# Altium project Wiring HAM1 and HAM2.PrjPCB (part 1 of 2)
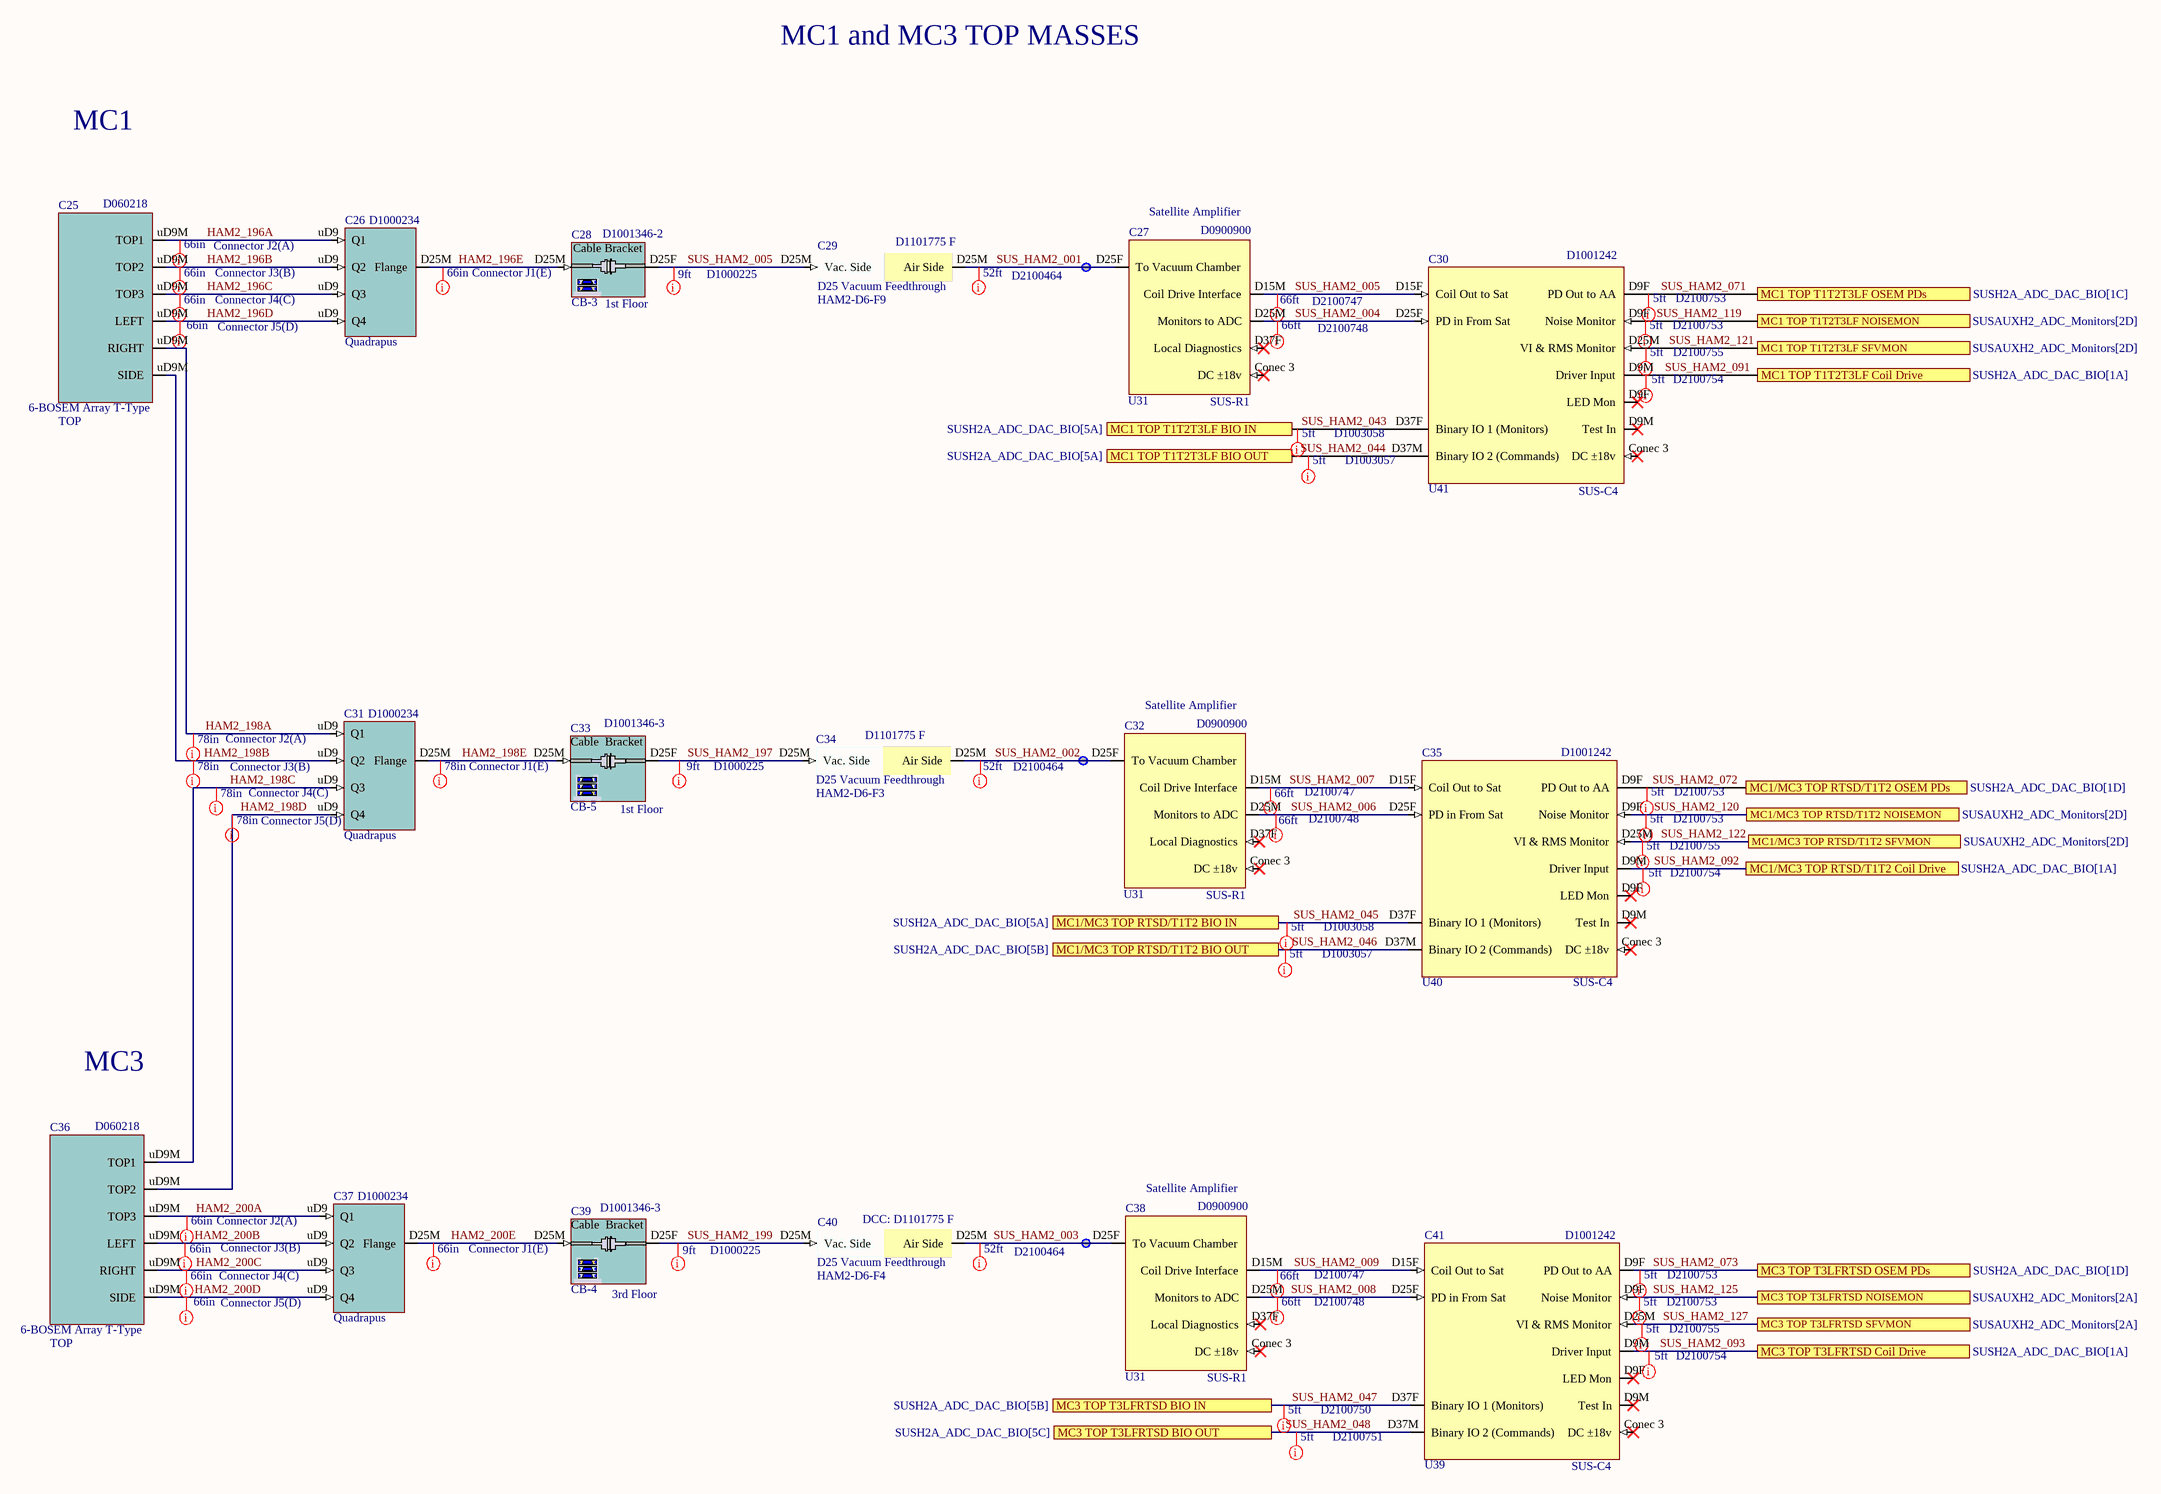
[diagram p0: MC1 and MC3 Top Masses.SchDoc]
14 sheets, 198 parts. Net scope: flat (ports and power ports of the same name join across sheets).
Sheets:
  MC1 and MC3 Top Masses.SchDoc
  PRM and PR3 Top Masses.SchDoc
  MC1 Middle and Bottom.SchDoc
  MC3 Middle and Bottom.SchDoc
  PRM Middle and Bottom.SchDoc
  PR3 Middle and Bottom.SchDoc
  IM1_IM2_IM3_IM4_OSEMs.SchDoc
  RM1_RM2.SchDoc
  JMX_PM1.SchDoc
  SUSH2A_ADC_DAC_BIO.SchDoc
  SUSH2B_ADC_DAC_BIO.SchDoc
  SUSAUXH2_ADC_Monitors.SchDoc
  RACK_SUS_R1_R2.SchDoc
  RACK_SUS_C3_C4.SchDoc

## Sheet MC1 and MC3 Top Masses.SchDoc: MC1 and MC3 Top Masses
size C; Organization: LIGO Laboratory; Address1: California Institute of Technology; Address2: Massachusetts Institute of Technology; DocumentNumber: D0902810; Revision: v11; SheetNumber: 1; SheetTotal: 14; Engineer: J.Kissel/L.Sánchez

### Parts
C25  6-BOSEM Array T-Type  Parameter 1: TOP  DCC: D060218
C26  Quadrapus  DCC: D1000234
C27  Satellite Amplifier  Slot: U31  Rack: SUS-R1  DCC: D0900900
C28  Rack: CB-3  Slot: 1st Floor  DCC: D1001346-2  (hidden comment: Cable Bracket)
C29  D25 Vacuum Feedthrough  value HAM2-D6-F9  DCC: D1101775 F
C30  Slot: U41  Rack: SUS-C4  DCC: D1001242  (hidden comment: CD Triple Top D1001242)
C31  Quadrapus  DCC: D1000234
C32  Satellite Amplifier  Slot: U31  Rack: SUS-R1  DCC: D0900900
C33  Rack: CB-5  Slot: 1st Floor  DCC: D1001346-3  (hidden comment: D1001346-3 1st Cable Bracket)
C34  D25 Vacuum Feedthrough  value HAM2-D6-F3  DCC: D1101775 F
C35  Slot: U40  Rack: SUS-C4  DCC: D1001242  (hidden comment: CD Triple Top D1001242)
C36  6-BOSEM Array T-Type  Parameter 1: TOP  DCC: D060218
C37  Quadrapus  DCC: D1000234
C38  Satellite Amplifier  Slot: U31  Rack: SUS-R1  DCC: D0900900
C39  Rack: CB-4  DCC: D1001346-3  Slot: 3rd Floor  (hidden comment: D1001346-3 3rd Cable Bracket)
C40  D25 Vacuum Feedthrough  value HAM2-D6-F4  DCC: D1101775 F
C41  Slot: U39  Rack: SUS-C4  DCC: D1001242  (hidden comment: CD Triple Top D1001242)

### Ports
MC1 TOP T1T2T3LF BIO IN (see SUSH2A_ADC_DAC_BIO[5A]), MC1 TOP T1T2T3LF BIO OUT (see SUSH2A_ADC_DAC_BIO[5A]), MC1 TOP T1T2T3LF Coil Drive (see SUSH2A_ADC_DAC_BIO[1A]), MC1 TOP T1T2T3LF NOISEMON (see SUSAUXH2_ADC_Monitors[2D]), MC1 TOP T1T2T3LF OSEM PDs (see SUSH2A_ADC_DAC_BIO[1C]), MC1 TOP T1T2T3LF SFVMON (see SUSAUXH2_ADC_Monitors[2D]), MC1/MC3 TOP RTSD/T1T2 BIO IN (see SUSH2A_ADC_DAC_BIO[5A]), MC1/MC3 TOP RTSD/T1T2 BIO OUT (see SUSH2A_ADC_DAC_BIO[5B]), MC1/MC3 TOP RTSD/T1T2 Coil Drive (see SUSH2A_ADC_DAC_BIO[1A]), MC1/MC3 TOP RTSD/T1T2 NOISEMON (see SUSAUXH2_ADC_Monitors[2D]), MC1/MC3 TOP RTSD/T1T2 OSEM PDs (see SUSH2A_ADC_DAC_BIO[1D]), MC1/MC3 TOP RTSD/T1T2 SFVMON (see SUSAUXH2_ADC_Monitors[2D]), MC3 TOP T3LFRTSD BIO IN (see SUSH2A_ADC_DAC_BIO[5B]), MC3 TOP T3LFRTSD BIO OUT (see SUSH2A_ADC_DAC_BIO[5C]), MC3 TOP T3LFRTSD Coil Drive (see SUSH2A_ADC_DAC_BIO[1A]), MC3 TOP T3LFRTSD NOISEMON (see SUSAUXH2_ADC_Monitors[2A]), MC3 TOP T3LFRTSD OSEM PDs (see SUSH2A_ADC_DAC_BIO[1D]), MC3 TOP T3LFRTSD SFVMON (see SUSAUXH2_ADC_Monitors[2A])

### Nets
HAM2_196A: C25.uD9M(TOP1) C26.uD9(Q1)
HAM2_196B: C25.uD9M(TOP2) C26.uD9(Q2)
HAM2_196C: C25.uD9M(TOP3) C26.uD9(Q3)
HAM2_196D: C25.uD9M(LEFT) C26.uD9(Q4)
HAM2_196E: C26.D25M(Flange) C28.D25M
HAM2_198A: C25.uD9M(RIGHT) C31.uD9(Q1)
HAM2_198B: C25.uD9M(SIDE) C31.uD9(Q2)
HAM2_198C: C31.uD9(Q3) C36.uD9M(TOP1)
HAM2_198D: C31.uD9(Q4) C36.uD9M(TOP2)
HAM2_198E: C31.D25M(Flange) C33.D25M
HAM2_200A: C36.uD9M(TOP3) C37.uD9(Q1)
HAM2_200B: C36.uD9M(LEFT) C37.uD9(Q2)
HAM2_200C: C36.uD9M(RIGHT) C37.uD9(Q3)
HAM2_200D: C36.uD9M(SIDE) C37.uD9(Q4)
HAM2_200E: C37.D25M(Flange) C39.D25M
SUS_HAM2_001: C27.D25F(To_Vacuum_Chamber) C29.D25M(Air_Side)
SUS_HAM2_002: C32.D25F(To_Vacuum_Chamber) C34.D25M(Air_Side)
SUS_HAM2_003: C38.D25F(To_Vacuum_Chamber) C40.D25M(Air_Side)
SUS_HAM2_004: C27.D25M(Monitors_to_ADC) C30.D25F(PD_in_From_Sat)
SUS_HAM2_005: C27.D15M(Coil_Drive_Interface) C28.D25F C29.D25M(Vac._Side) C30.D15F(Coil_Out_to_Sat)
SUS_HAM2_006: C32.D25M(Monitors_to_ADC) C35.D25F(PD_in_From_Sat)
SUS_HAM2_007: C32.D15M(Coil_Drive_Interface) C35.D15F(Coil_Out_to_Sat)
SUS_HAM2_008: C38.D25M(Monitors_to_ADC) C41.D25F(PD_in_From_Sat)
SUS_HAM2_009: C38.D15M(Coil_Drive_Interface) C41.D15F(Coil_Out_to_Sat)
SUS_HAM2_043: C30.D37F(Binary_IO_1_(Monitors)) ; port MC1 TOP T1T2T3LF BIO IN
SUS_HAM2_044: C30.D37M(Binary_IO_2_(Commands)) ; port MC1 TOP T1T2T3LF BIO OUT
SUS_HAM2_045: C35.D37F(Binary_IO_1_(Monitors)) ; port MC1/MC3 TOP RTSD/T1T2 BIO IN
SUS_HAM2_046: C35.D37M(Binary_IO_2_(Commands)) ; port MC1/MC3 TOP RTSD/T1T2 BIO OUT
SUS_HAM2_047: C41.D37F(Binary_IO_1_(Monitors)) ; port MC3 TOP T3LFRTSD BIO IN
SUS_HAM2_048: C41.D37M(Binary_IO_2_(Commands)) ; port MC3 TOP T3LFRTSD BIO OUT
SUS_HAM2_071: C30.D9F(PD_Out_to_AA) ; port MC1 TOP T1T2T3LF OSEM PDs
SUS_HAM2_072: C35.D9F(PD_Out_to_AA) ; port MC1/MC3 TOP RTSD/T1T2 OSEM PDs
SUS_HAM2_073: C41.D9F(PD_Out_to_AA) ; port MC3 TOP T3LFRTSD OSEM PDs
SUS_HAM2_091: C30.D9M(Test_In) ; port MC1 TOP T1T2T3LF Coil Drive
SUS_HAM2_092: C35.D9M(Test_In) ; port MC1/MC3 TOP RTSD/T1T2 Coil Drive
SUS_HAM2_093: C41.D9M(Test_In) ; port MC3 TOP T3LFRTSD Coil Drive
SUS_HAM2_119: C30.D9F(Noise_Monitor) ; port MC1 TOP T1T2T3LF NOISEMON
SUS_HAM2_120: C35.D9F(Noise_Monitor) ; port MC1/MC3 TOP RTSD/T1T2 NOISEMON
SUS_HAM2_121: C30.D25M(VI_&_RMS_Monitor) ; port MC1 TOP T1T2T3LF SFVMON
SUS_HAM2_122: C35.D25M(VI_&_RMS_Monitor) ; port MC1/MC3 TOP RTSD/T1T2 SFVMON
SUS_HAM2_125: C41.D9F(Noise_Monitor) ; port MC3 TOP T3LFRTSD NOISEMON
SUS_HAM2_127: C41.D25M(VI_&_RMS_Monitor) ; port MC3 TOP T3LFRTSD SFVMON
SUS_HAM2_197: C33.D25F C34.D25M(Vac._Side)
SUS_HAM2_199: C39.D25F C40.D25M(Vac._Side)

Not connected (* = marked no-connect by the designer): C27 Conec 3(DC_±18v)* D37F(Local_Diagnostics)*; C30 Conec 3(DC_±18v)*; C32 Conec 3(DC_±18v)* D37F(Local_Diagnostics)*; C35 Conec 3(DC_±18v)*; C38 Conec 3(DC_±18v)* D37F(Local_Diagnostics)*; C41 Conec 3(DC_±18v)*

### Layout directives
Length: 5ft; DCC: D2100755: SUS_HAM2_121, SUS_HAM2_122, SUS_HAM2_127
Length: 5ft; DCC: D2100753: SUS_HAM2_071, SUS_HAM2_072, SUS_HAM2_073, SUS_HAM2_119, SUS_HAM2_120, SUS_HAM2_125
Length: 66in; DCC: Connector J2(A): HAM2_196A, HAM2_200A
Length: 66in; DCC: Connector J1(E): HAM2_196E, HAM2_200E
Length: 9ft; DCC: D1000225: SUS_HAM2_005, SUS_HAM2_197, SUS_HAM2_199
Length: 52ft; DCC: D2100464: SUS_HAM2_001, SUS_HAM2_002, SUS_HAM2_003
Length: 5ft; DCC: D1003058: SUS_HAM2_043, SUS_HAM2_045
Length: 5ft; DCC: D1003057: SUS_HAM2_044, SUS_HAM2_046
Length: 5ft; DCC: D2100754: SUS_HAM2_091, SUS_HAM2_092, SUS_HAM2_093
Length: 66in; DCC: Connector J3(B): HAM2_196B, HAM2_200B
Length: 66in; DCC: Connector J4(C): HAM2_196C, HAM2_200C
Length: 66in; DCC: Connector J5(D): HAM2_196D, HAM2_200D
Length: 78in; DCC: Connector J2(A): HAM2_198A
Length: 78in; DCC: Connector J3(B): HAM2_198B
Length: 78in; DCC: Connector J1(E): HAM2_198E
Length: 66ft; DCC: D2100747: SUS_HAM2_005, SUS_HAM2_007, SUS_HAM2_009
Length: 66ft; DCC: D2100748: SUS_HAM2_004, SUS_HAM2_006, SUS_HAM2_008
Length: 78in; DCC: Connector J5(D): HAM2_198D
Length: 78in; DCC: Connector J4(C): HAM2_198C
Length: 5ft; DCC: D2100751: SUS_HAM2_048
Length: 5ft; DCC: D2100750: SUS_HAM2_047

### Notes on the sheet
- MC1 and MC3 TOP MASSES
- MC1
- MC3

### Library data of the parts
C25 C36 = 6-BOSEM Array T-Type: Serial: Sxxxxxxx; System: SUS; Slot: U?; Rack: SUS-R?
C26 C31 C37 = D1000234 D25 Quadrapus: Slot: U?; Rack: R?; Serial: Sxxxxxxx; System: SUS
C27 C32 C38 = Satellite Amplifier: System: SUS; Serial: Sxxxxxxx
C28 = D1001346-2 1st Cable Bracket: D1001346-2 1/2 Cable Bracket for HAM Tables; Serial: Sxxxxxxx; System: SUS
C29 C34 C40 = VacFeedD25: Serial: Sxxxxxxx; System: ISC; Rack: R?; Slot: U?
C30 C35 C41 = CD Triple Top D1001242: System: SUS; Serial: Sxxxxxxx
C33 = D1001346-3 1st Cable Bracket: D1001346-3 1st Cable Bracket  for HAM Tables; Serial: Sxxxxxxx; System: SUS
C39 = D1001346-3 3rd Cable Bracket: D1001346-3 3rd Cable Bracket for HAM Tables; Serial: Sxxxxxxx; System: SUS

## Sheet PRM and PR3 Top Masses.SchDoc: PRM and PR3 Top Masses
size C; Organization: LIGO Laboratory; Address1: California Institute of Technology; Address2: Massachusetts Institute of Technology; DocumentNumber: D0902810; Revision: v11; SheetNumber: 2; SheetTotal: 14; Engineer: J.Kissel/L.Sánchez
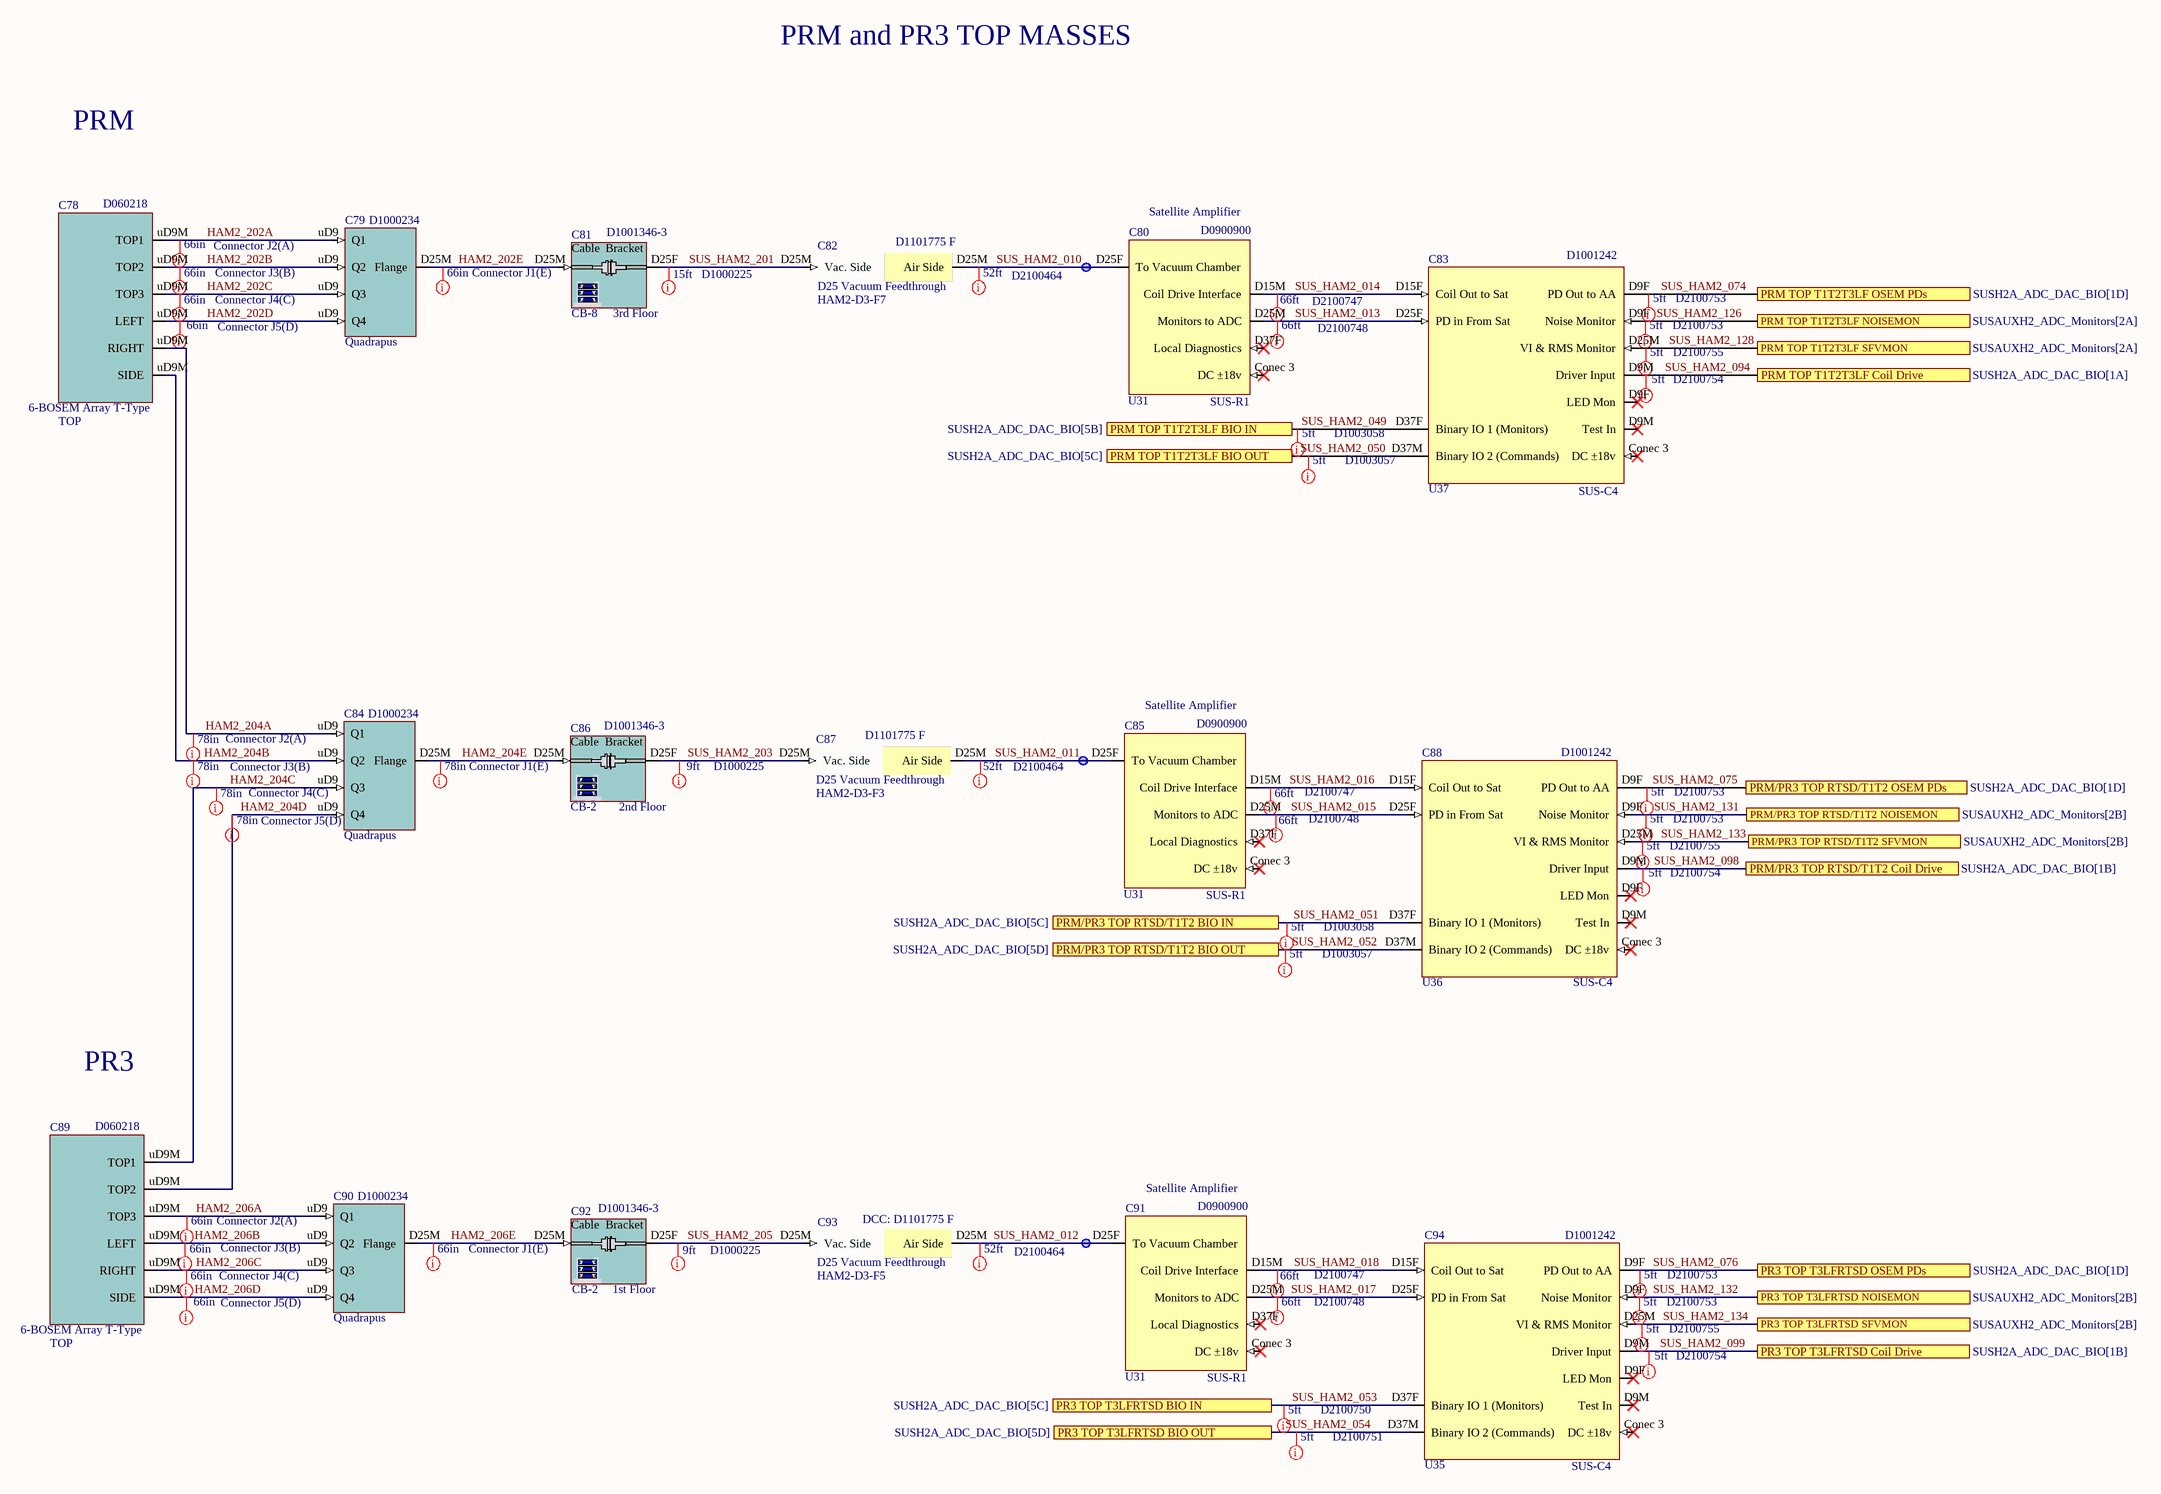
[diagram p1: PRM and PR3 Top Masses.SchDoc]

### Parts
C78  6-BOSEM Array T-Type  Parameter 1: TOP  DCC: D060218
C79  Quadrapus  DCC: D1000234
C80  Satellite Amplifier  Slot: U31  Rack: SUS-R1  DCC: D0900900
C81  Rack: CB-8  DCC: D1001346-3  Slot: 3rd Floor  (hidden comment: D1001346-3 3rd Cable Bracket)
C82  D25 Vacuum Feedthrough  value HAM2-D3-F7  DCC: D1101775 F
C83  Slot: U37  Rack: SUS-C4  DCC: D1001242  (hidden comment: CD Triple Top D1001242)
C84  Quadrapus  DCC: D1000234
C85  Satellite Amplifier  Slot: U31  Rack: SUS-R1  DCC: D0900900
C86  Rack: CB-2  DCC: D1001346-3  Slot: 2nd Floor  (hidden comment: D1001346-3 2nd Cable Bracket)
C87  D25 Vacuum Feedthrough  value HAM2-D3-F3  DCC: D1101775 F
C88  Slot: U36  Rack: SUS-C4  DCC: D1001242  (hidden comment: CD Triple Top D1001242)
C89  6-BOSEM Array T-Type  Parameter 1: TOP  DCC: D060218
C90  Quadrapus  DCC: D1000234
C91  Satellite Amplifier  Slot: U31  Rack: SUS-R1  DCC: D0900900
C92  Rack: CB-2  Slot: 1st Floor  DCC: D1001346-3  (hidden comment: D1001346-3 1st Cable Bracket)
C93  D25 Vacuum Feedthrough  value HAM2-D3-F5  DCC: D1101775 F
C94  Slot: U35  Rack: SUS-C4  DCC: D1001242  (hidden comment: CD Triple Top D1001242)

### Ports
PR3 TOP T3LFRTSD BIO IN (see SUSH2A_ADC_DAC_BIO[5C]), PR3 TOP T3LFRTSD BIO OUT (see SUSH2A_ADC_DAC_BIO[5D]), PR3 TOP T3LFRTSD Coil Drive (see SUSH2A_ADC_DAC_BIO[1B]), PR3 TOP T3LFRTSD NOISEMON (see SUSAUXH2_ADC_Monitors[2B]), PR3 TOP T3LFRTSD OSEM PDs (see SUSH2A_ADC_DAC_BIO[1D]), PR3 TOP T3LFRTSD SFVMON (see SUSAUXH2_ADC_Monitors[2B]), PRM TOP T1T2T3LF BIO IN (see SUSH2A_ADC_DAC_BIO[5B]), PRM TOP T1T2T3LF BIO OUT (see SUSH2A_ADC_DAC_BIO[5C]), PRM TOP T1T2T3LF Coil Drive (see SUSH2A_ADC_DAC_BIO[1A]), PRM TOP T1T2T3LF NOISEMON (see SUSAUXH2_ADC_Monitors[2A]), PRM TOP T1T2T3LF OSEM PDs (see SUSH2A_ADC_DAC_BIO[1D]), PRM TOP T1T2T3LF SFVMON (see SUSAUXH2_ADC_Monitors[2A]), PRM/PR3 TOP RTSD/T1T2 BIO IN (see SUSH2A_ADC_DAC_BIO[5C]), PRM/PR3 TOP RTSD/T1T2 BIO OUT (see SUSH2A_ADC_DAC_BIO[5D]), PRM/PR3 TOP RTSD/T1T2 Coil Drive (see SUSH2A_ADC_DAC_BIO[1B]), PRM/PR3 TOP RTSD/T1T2 NOISEMON (see SUSAUXH2_ADC_Monitors[2B]), PRM/PR3 TOP RTSD/T1T2 OSEM PDs (see SUSH2A_ADC_DAC_BIO[1D]), PRM/PR3 TOP RTSD/T1T2 SFVMON (see SUSAUXH2_ADC_Monitors[2B])

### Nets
HAM2_202A: C78.uD9M(TOP1) C79.uD9(Q1)
HAM2_202B: C78.uD9M(TOP2) C79.uD9(Q2)
HAM2_202C: C78.uD9M(TOP3) C79.uD9(Q3)
HAM2_202D: C78.uD9M(LEFT) C79.uD9(Q4)
HAM2_202E: C79.D25M(Flange) C81.D25M
HAM2_204A: C78.uD9M(RIGHT) C84.uD9(Q1)
HAM2_204B: C78.uD9M(SIDE) C84.uD9(Q2)
HAM2_204C: C84.uD9(Q3) C89.uD9M(TOP1)
HAM2_204D: C84.uD9(Q4) C89.uD9M(TOP2)
HAM2_204E: C84.D25M(Flange) C86.D25M
HAM2_206A: C89.uD9M(TOP3) C90.uD9(Q1)
HAM2_206B: C89.uD9M(LEFT) C90.uD9(Q2)
HAM2_206C: C89.uD9M(RIGHT) C90.uD9(Q3)
HAM2_206D: C89.uD9M(SIDE) C90.uD9(Q4)
HAM2_206E: C90.D25M(Flange) C92.D25M
SUS_HAM2_010: C80.D25F(To_Vacuum_Chamber) C82.D25M(Air_Side)
SUS_HAM2_011: C85.D25F(To_Vacuum_Chamber) C87.D25M(Air_Side)
SUS_HAM2_012: C91.D25F(To_Vacuum_Chamber) C93.D25M(Air_Side)
SUS_HAM2_013: C80.D25M(Monitors_to_ADC) C83.D25F(PD_in_From_Sat)
SUS_HAM2_014: C80.D15M(Coil_Drive_Interface) C83.D15F(Coil_Out_to_Sat)
SUS_HAM2_015: C85.D25M(Monitors_to_ADC) C88.D25F(PD_in_From_Sat)
SUS_HAM2_016: C85.D15M(Coil_Drive_Interface) C88.D15F(Coil_Out_to_Sat)
SUS_HAM2_017: C91.D25M(Monitors_to_ADC) C94.D25F(PD_in_From_Sat)
SUS_HAM2_018: C91.D15M(Coil_Drive_Interface) C94.D15F(Coil_Out_to_Sat)
SUS_HAM2_049: C83.D37F(Binary_IO_1_(Monitors)) ; port PRM TOP T1T2T3LF BIO IN
SUS_HAM2_050: C83.D37M(Binary_IO_2_(Commands)) ; port PRM TOP T1T2T3LF BIO OUT
SUS_HAM2_051: C88.D37F(Binary_IO_1_(Monitors)) ; port PRM/PR3 TOP RTSD/T1T2 BIO IN
SUS_HAM2_052: C88.D37M(Binary_IO_2_(Commands)) ; port PRM/PR3 TOP RTSD/T1T2 BIO OUT
SUS_HAM2_053: C94.D37F(Binary_IO_1_(Monitors)) ; port PR3 TOP T3LFRTSD BIO IN
SUS_HAM2_054: C94.D37M(Binary_IO_2_(Commands)) ; port PR3 TOP T3LFRTSD BIO OUT
SUS_HAM2_074: C83.D9F(PD_Out_to_AA) ; port PRM TOP T1T2T3LF OSEM PDs
SUS_HAM2_075: C88.D9F(PD_Out_to_AA) ; port PRM/PR3 TOP RTSD/T1T2 OSEM PDs
SUS_HAM2_076: C94.D9F(PD_Out_to_AA) ; port PR3 TOP T3LFRTSD OSEM PDs
SUS_HAM2_094: C83.D9M(Test_In) ; port PRM TOP T1T2T3LF Coil Drive
SUS_HAM2_098: C88.D9M(Test_In) ; port PRM/PR3 TOP RTSD/T1T2 Coil Drive
SUS_HAM2_099: C94.D9M(Test_In) ; port PR3 TOP T3LFRTSD Coil Drive
SUS_HAM2_126: C83.D9F(Noise_Monitor) ; port PRM TOP T1T2T3LF NOISEMON
SUS_HAM2_128: C83.D25M(VI_&_RMS_Monitor) ; port PRM TOP T1T2T3LF SFVMON
SUS_HAM2_131: C88.D9F(Noise_Monitor) ; port PRM/PR3 TOP RTSD/T1T2 NOISEMON
SUS_HAM2_132: C94.D9F(Noise_Monitor) ; port PR3 TOP T3LFRTSD NOISEMON
SUS_HAM2_133: C88.D25M(VI_&_RMS_Monitor) ; port PRM/PR3 TOP RTSD/T1T2 SFVMON
SUS_HAM2_134: C94.D25M(VI_&_RMS_Monitor) ; port PR3 TOP T3LFRTSD SFVMON
SUS_HAM2_201: C81.D25F C82.D25M(Vac._Side)
SUS_HAM2_203: C86.D25F C87.D25M(Vac._Side)
SUS_HAM2_205: C92.D25F C93.D25M(Vac._Side)

Not connected (* = marked no-connect by the designer): C80 Conec 3(DC_±18v)* D37F(Local_Diagnostics)*; C83 Conec 3(DC_±18v)*; C85 Conec 3(DC_±18v)* D37F(Local_Diagnostics)*; C88 Conec 3(DC_±18v)*; C91 Conec 3(DC_±18v)* D37F(Local_Diagnostics)*; C94 Conec 3(DC_±18v)*

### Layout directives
Length: 5ft; DCC: D2100755: SUS_HAM2_128, SUS_HAM2_133, SUS_HAM2_134
Length: 5ft; DCC: D2100753: SUS_HAM2_074, SUS_HAM2_075, SUS_HAM2_076, SUS_HAM2_126, SUS_HAM2_131, SUS_HAM2_132
Length: 66in; DCC: Connector J2(A): HAM2_202A, HAM2_206A
Length: 66in; DCC: Connector J1(E): HAM2_202E, HAM2_206E
Length: 52ft; DCC: D2100464: SUS_HAM2_010, SUS_HAM2_011, SUS_HAM2_012
Length: 5ft; DCC: D1003058: SUS_HAM2_049, SUS_HAM2_051
Length: 5ft; DCC: D1003057: SUS_HAM2_050, SUS_HAM2_052
Length: 5ft; DCC: D2100754: SUS_HAM2_094, SUS_HAM2_098, SUS_HAM2_099
Length: 66in; DCC: Connector J3(B): HAM2_202B, HAM2_206B
Length: 66in; DCC: Connector J4(C): HAM2_202C, HAM2_206C
Length: 66in; DCC: Connector J5(D): HAM2_202D, HAM2_206D
Length: 78in; DCC: Connector J2(A): HAM2_204A
Length: 78in; DCC: Connector J3(B): HAM2_204B
Length: 78in; DCC: Connector J1(E): HAM2_204E
Length: 66ft; DCC: D2100747: SUS_HAM2_014, SUS_HAM2_016, SUS_HAM2_018
Length: 66ft; DCC: D2100748: SUS_HAM2_013, SUS_HAM2_015, SUS_HAM2_017
Length: 78in; DCC: Connector J5(D): HAM2_204D
Length: 78in; DCC: Connector J4(C): HAM2_204C
Length: 5ft; DCC: D2100751: SUS_HAM2_054
Length: 5ft; DCC: D2100750: SUS_HAM2_053
Length: 9ft; DCC: D1000225: SUS_HAM2_203, SUS_HAM2_205
Length: 15ft; DCC: D1000225: SUS_HAM2_201

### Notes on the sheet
- PRM and PR3 TOP MASSES
- PRM
- PR3

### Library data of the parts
C78 C89 = 6-BOSEM Array T-Type: as C25 on sheet MC1 and MC3 Top Masses
C79 C84 C90 = D1000234 D25 Quadrapus: as C26 on sheet MC1 and MC3 Top Masses
C80 C85 C91 = Satellite Amplifier: System: SUS; Serial: Sxxxxxxx
C81 = D1001346-3 3rd Cable Bracket: as C39 on sheet MC1 and MC3 Top Masses
C82 C87 C93 = VacFeedD25: as C29 on sheet MC1 and MC3 Top Masses
C83 C88 C94 = CD Triple Top D1001242: System: SUS; Serial: Sxxxxxxx
C86 = D1001346-3 2nd Cable Bracket: D1001346-3 2nd Cable Bracket  for HAM Tables; Serial: Sxxxxxxx; System: SUS
C92 = D1001346-3 1st Cable Bracket: as C33 on sheet MC1 and MC3 Top Masses

## Sheet MC1 Middle and Bottom.SchDoc: MC1 Middle and Bottom
size C; Organization: LIGO Laboratory; Address1: California Institute of Technology; Address2: Massachusetts Institute of Technology; DocumentNumber: D0902810; Revision: v11; SheetNumber: 3; SheetTotal: 14; Engineer: J.Kissel/L.Sánchez
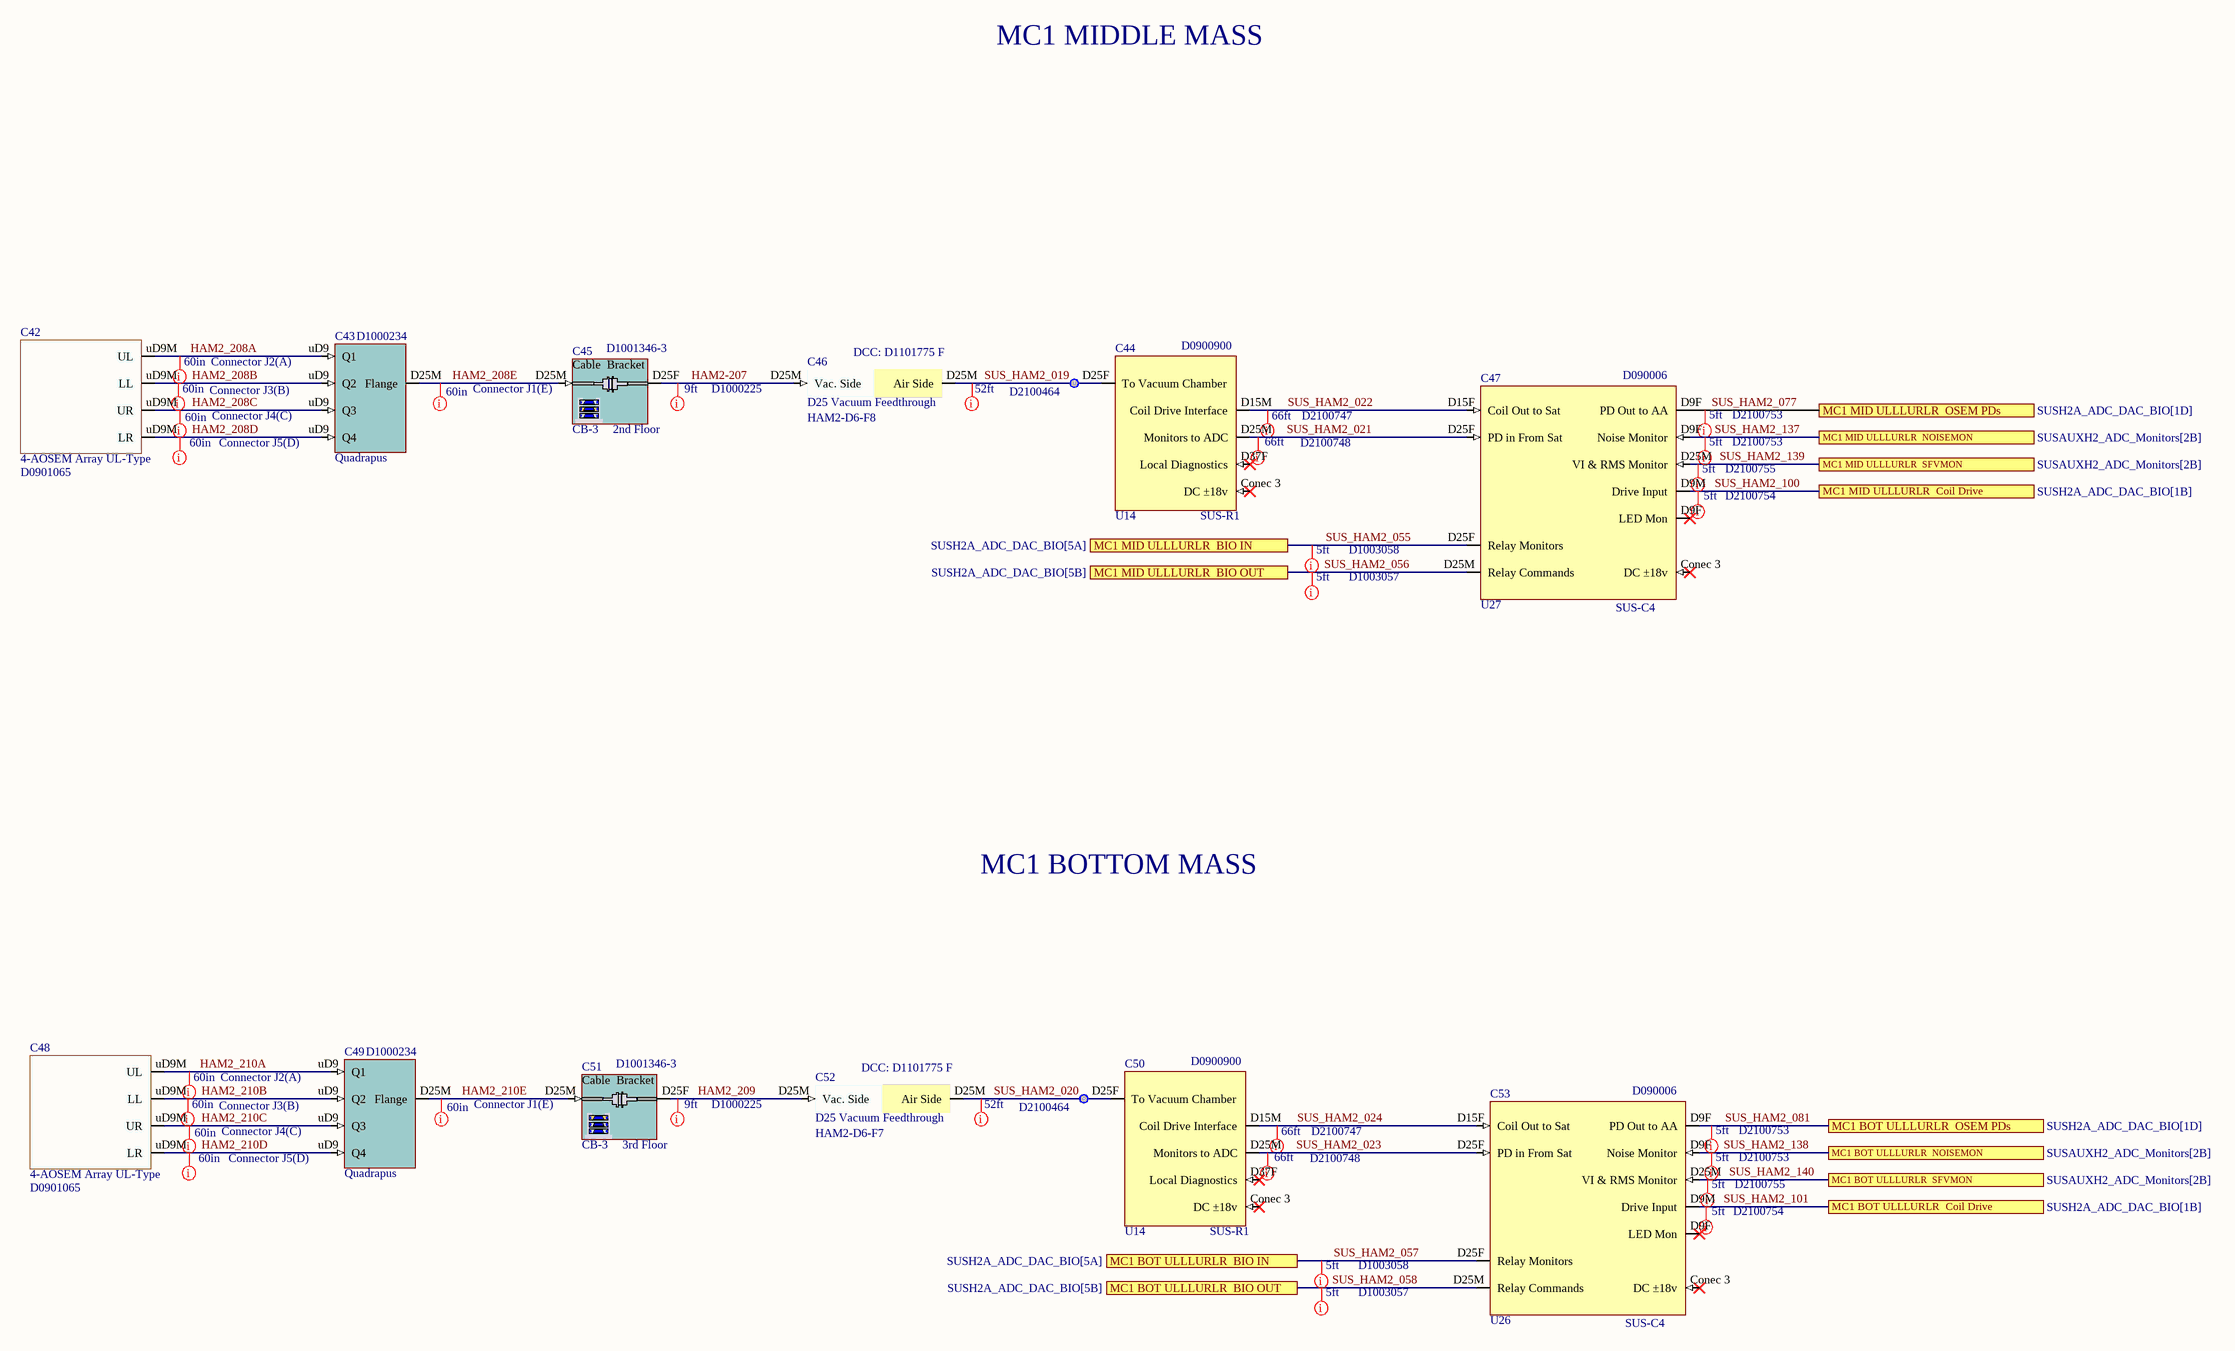
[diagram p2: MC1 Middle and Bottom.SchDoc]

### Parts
C42  4-AOSEM Array UL-Type  DCC: D0901065
C43  Quadrapus  DCC: D1000234
C44  Slot: U14  Rack: SUS-R1  DCC: D0900900  (hidden comment: Satellite Amplifier UK D0900900)
C45  Rack: CB-3  DCC: D1001346-3  Slot: 2nd Floor  (hidden comment: D1001346-3 2nd Cable Bracket)
C46  D25 Vacuum Feedthrough  value HAM2-D6-F8  DCC: D1101775 F
C47  Slot: U27  Rack: SUS-C4  DCC: D090006  (hidden comment: CD Triple Acq D090006)
C48  4-AOSEM Array UL-Type  DCC: D0901065
C49  Quadrapus  DCC: D1000234
C50  Slot: U14  Rack: SUS-R1  DCC: D0900900  (hidden comment: Satellite Amplifier UK D0900900)
C51  Rack: CB-3  DCC: D1001346-3  Slot: 3rd Floor  (hidden comment: D1001346-3 3rd Cable Bracket)
C52  D25 Vacuum Feedthrough  value HAM2-D6-F7  DCC: D1101775 F
C53  Slot: U26  Rack: SUS-C4  DCC: D090006  (hidden comment: CD Triple Acq D090006)

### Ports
MC1 BOT ULLLURLR  BIO IN (see SUSH2A_ADC_DAC_BIO[5A]), MC1 BOT ULLLURLR  BIO OUT (see SUSH2A_ADC_DAC_BIO[5B]), MC1 BOT ULLLURLR  Coil Drive (see SUSH2A_ADC_DAC_BIO[1B]), MC1 BOT ULLLURLR  NOISEMON (see SUSAUXH2_ADC_Monitors[2B]), MC1 BOT ULLLURLR  OSEM PDs (see SUSH2A_ADC_DAC_BIO[1D]), MC1 BOT ULLLURLR  SFVMON (see SUSAUXH2_ADC_Monitors[2B]), MC1 MID ULLLURLR  BIO IN (see SUSH2A_ADC_DAC_BIO[5A]), MC1 MID ULLLURLR  BIO OUT (see SUSH2A_ADC_DAC_BIO[5B]), MC1 MID ULLLURLR  Coil Drive (see SUSH2A_ADC_DAC_BIO[1B]), MC1 MID ULLLURLR  NOISEMON (see SUSAUXH2_ADC_Monitors[2B]), MC1 MID ULLLURLR  OSEM PDs (see SUSH2A_ADC_DAC_BIO[1D]), MC1 MID ULLLURLR  SFVMON (see SUSAUXH2_ADC_Monitors[2B])

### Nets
HAM2-207: C45.D25F C46.D25M(Vac._Side)
HAM2_208A: C42.uD9M(UL) C43.uD9(Q1)
HAM2_208B: C42.uD9M(LL) C43.uD9(Q2)
HAM2_208C: C42.uD9M(UR) C43.uD9(Q3)
HAM2_208D: C42.uD9M(LR) C43.uD9(Q4)
HAM2_208E: C43.D25M(Flange) C45.D25M
HAM2_209: C51.D25F C52.D25M(Vac._Side)
HAM2_210A: C48.uD9M(UL) C49.uD9(Q1)
HAM2_210B: C48.uD9M(LL) C49.uD9(Q2)
HAM2_210C: C48.uD9M(UR) C49.uD9(Q3)
HAM2_210D: C48.uD9M(LR) C49.uD9(Q4)
HAM2_210E: C49.D25M(Flange) C51.D25M
SUS_HAM2_019: C44.D25F(To_Vacuum_Chamber) C46.D25M(Air_Side)
SUS_HAM2_020: C50.D25F(To_Vacuum_Chamber) C52.D25M(Air_Side)
SUS_HAM2_021: C44.D25M(Monitors_to_ADC) C47.D25F(PD_in_From_Sat)
SUS_HAM2_022: C44.D15M(Coil_Drive_Interface) C47.D15F(Coil_Out_to_Sat)
SUS_HAM2_023: C50.D25M(Monitors_to_ADC) C53.D25F(PD_in_From_Sat)
SUS_HAM2_024: C50.D15M(Coil_Drive_Interface) C53.D15F(Coil_Out_to_Sat)
SUS_HAM2_055: C47.D25F(Relay_Monitors) ; port MC1 MID ULLLURLR  BIO IN
SUS_HAM2_056: C47.D25M(Relay_Commands) ; port MC1 MID ULLLURLR  BIO OUT
SUS_HAM2_057: C53.D25F(Relay_Monitors) ; port MC1 BOT ULLLURLR  BIO IN
SUS_HAM2_058: C53.D25M(Relay_Commands) ; port MC1 BOT ULLLURLR  BIO OUT
SUS_HAM2_077: C47.D9F(PD_Out_to_AA) ; port MC1 MID ULLLURLR  OSEM PDs
SUS_HAM2_081: C53.D9F(PD_Out_to_AA) ; port MC1 BOT ULLLURLR  OSEM PDs
SUS_HAM2_100: C47.D9M(Drive_Input) ; port MC1 MID ULLLURLR  Coil Drive
SUS_HAM2_101: C53.D9M(Drive_Input) ; port MC1 BOT ULLLURLR  Coil Drive
SUS_HAM2_137: C47.D9F(Noise_Monitor) ; port MC1 MID ULLLURLR  NOISEMON
SUS_HAM2_138: C53.D9F(Noise_Monitor) ; port MC1 BOT ULLLURLR  NOISEMON
SUS_HAM2_139: C47.D25M(VI_&_RMS_Monitor) ; port MC1 MID ULLLURLR  SFVMON
SUS_HAM2_140: C53.D25M(VI_&_RMS_Monitor) ; port MC1 BOT ULLLURLR  SFVMON

Not connected (* = marked no-connect by the designer): C44 Conec 3(DC_±18v)* D37F(Local_Diagnostics)*; C47 Conec 3(DC_±18v)*; C50 Conec 3(DC_±18v)* D37F(Local_Diagnostics)*; C53 Conec 3(DC_±18v)*

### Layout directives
Length: 52ft; DCC: D2100464: SUS_HAM2_019, SUS_HAM2_020
Length: 5ft; DCC: D2100753: SUS_HAM2_077, SUS_HAM2_081, SUS_HAM2_137, SUS_HAM2_138
Length: 5ft; DCC: D2100754: SUS_HAM2_100, SUS_HAM2_101
Length: 5ft; DCC: D2100755: SUS_HAM2_139, SUS_HAM2_140
Length: 60in; DCC: Connector J5(D): HAM2_208D, HAM2_210D
Length: 60in; DCC: Connector J4(C): HAM2_208C, HAM2_210C
Length: 60in; DCC: Connector J3(B): HAM2_208B, HAM2_210B
Length: 60in; DCC: Connector J2(A): HAM2_208A, HAM2_210A
Length: 66ft; DCC: D2100747: SUS_HAM2_022, SUS_HAM2_024
Length: 66ft; DCC: D2100748: SUS_HAM2_021, SUS_HAM2_023
Length: 5ft; DCC: D1003058: SUS_HAM2_055, SUS_HAM2_057
Length: 5ft; DCC: D1003057: SUS_HAM2_056, SUS_HAM2_058
Length: 60in; DCC: Connector J1(E): HAM2_208E, HAM2_210E
Length: 9ft; DCC: D1000225: HAM2-207, HAM2_209

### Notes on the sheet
- MC1 MIDDLE MASS
- MC1 BOTTOM MASS

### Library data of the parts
C42 C48 = 4-AOSEM Array UL-Type: Rack: R?; Slot: U?; Serial: Sxxxxxxx; System: SUS
C43 C49 = D1000234 D25 Quadrapus: as C26 on sheet MC1 and MC3 Top Masses
C44 C50 = Satellite Amplifier UK D0900900: System: SUS; Serial: Sxxxxxxx
C45 = D1001346-3 2nd Cable Bracket: as C86 on sheet PRM and PR3 Top Masses
C46 C52 = VacFeedD25: as C29 on sheet MC1 and MC3 Top Masses
C47 C53 = CD Triple Acq D090006: System: SUS; Serial: Sxxxxxxx
C51 = D1001346-3 3rd Cable Bracket: as C39 on sheet MC1 and MC3 Top Masses

## Sheet MC3 Middle and Bottom.SchDoc: MC3 Middle and Bottom
size C; Organization: LIGO Laboratory; Address1: California Institute of Technology; Address2: Massachusetts Institute of Technology; DocumentNumber: D0902810; Revision: v11; SheetNumber: 4; SheetTotal: 14; Engineer: J.Kissel/L.Sánchez
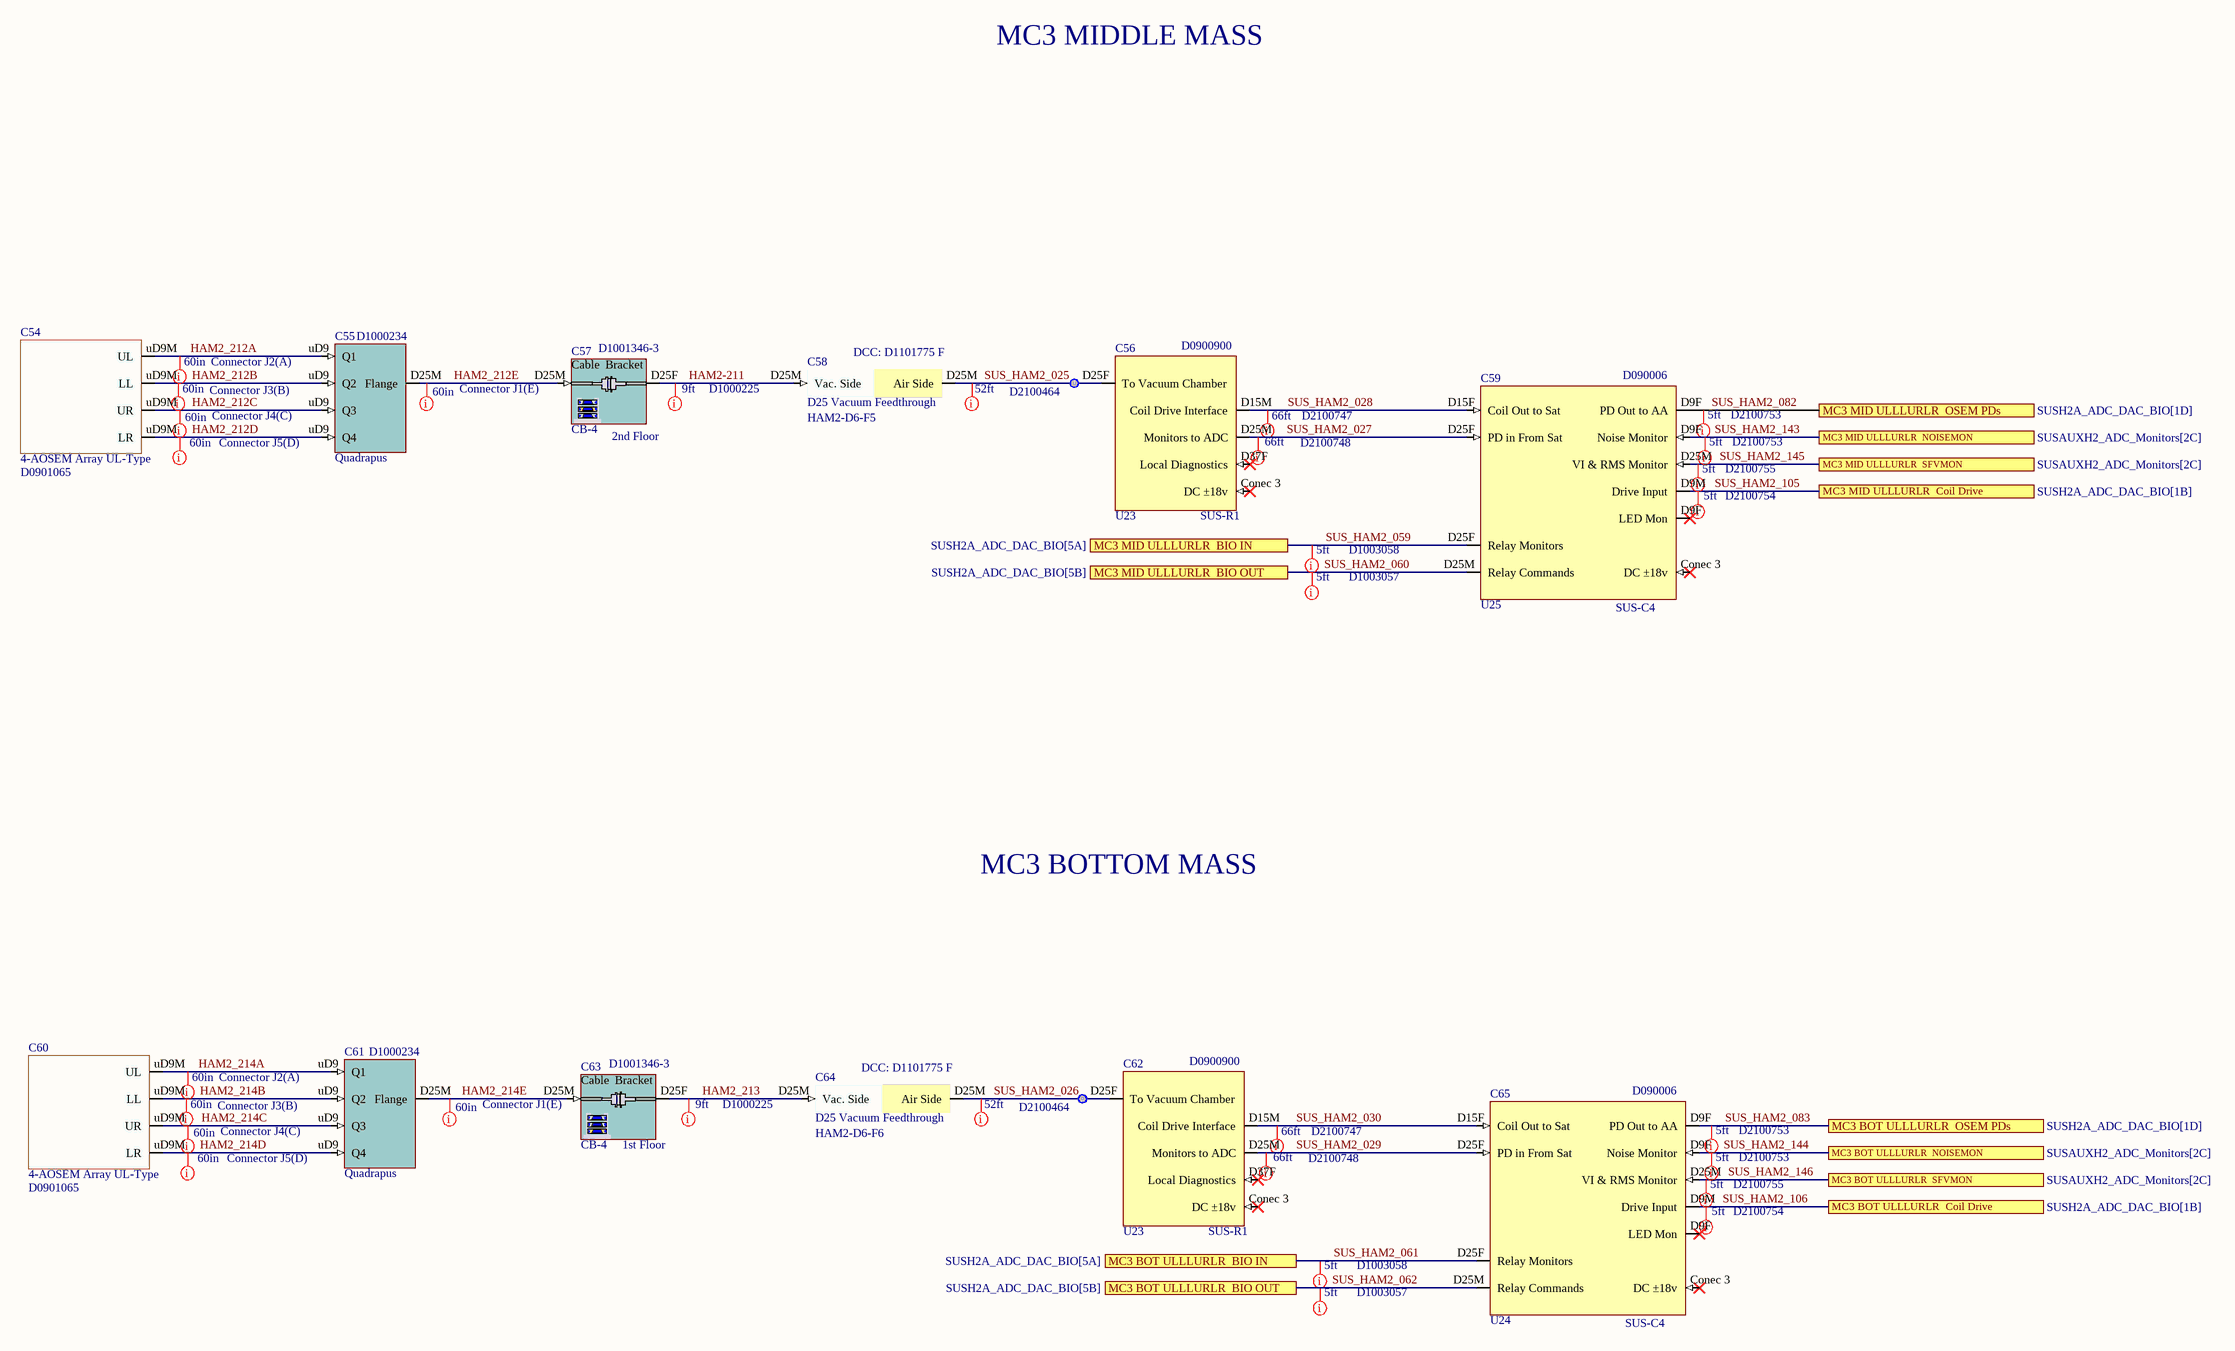
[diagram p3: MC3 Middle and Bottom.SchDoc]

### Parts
C54  4-AOSEM Array UL-Type  DCC: D0901065
C55  Quadrapus  DCC: D1000234
C56  Slot: U23  Rack: SUS-R1  DCC: D0900900  (hidden comment: Satellite Amplifier UK D0900900)
C57  Rack: CB-4  DCC: D1001346-3  Slot: 2nd Floor  (hidden comment: D1001346-3 2nd Cable Bracket)
C58  D25 Vacuum Feedthrough  value HAM2-D6-F5  DCC: D1101775 F
C59  Slot: U25  Rack: SUS-C4  DCC: D090006  (hidden comment: CD Triple Acq D090006)
C60  4-AOSEM Array UL-Type  DCC: D0901065
C61  Quadrapus  DCC: D1000234
C62  Slot: U23  Rack: SUS-R1  DCC: D0900900  (hidden comment: Satellite Amplifier UK D0900900)
C63  Rack: CB-4  Slot: 1st Floor  DCC: D1001346-3  (hidden comment: D1001346-3 1st Cable Bracket)
C64  D25 Vacuum Feedthrough  value HAM2-D6-F6  DCC: D1101775 F
C65  Slot: U24  Rack: SUS-C4  DCC: D090006  (hidden comment: CD Triple Acq D090006)

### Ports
MC3 BOT ULLLURLR  BIO IN (see SUSH2A_ADC_DAC_BIO[5A]), MC3 BOT ULLLURLR  BIO OUT (see SUSH2A_ADC_DAC_BIO[5B]), MC3 BOT ULLLURLR  Coil Drive (see SUSH2A_ADC_DAC_BIO[1B]), MC3 BOT ULLLURLR  NOISEMON (see SUSAUXH2_ADC_Monitors[2C]), MC3 BOT ULLLURLR  OSEM PDs (see SUSH2A_ADC_DAC_BIO[1D]), MC3 BOT ULLLURLR  SFVMON (see SUSAUXH2_ADC_Monitors[2C]), MC3 MID ULLLURLR  BIO IN (see SUSH2A_ADC_DAC_BIO[5A]), MC3 MID ULLLURLR  BIO OUT (see SUSH2A_ADC_DAC_BIO[5B]), MC3 MID ULLLURLR  Coil Drive (see SUSH2A_ADC_DAC_BIO[1B]), MC3 MID ULLLURLR  NOISEMON (see SUSAUXH2_ADC_Monitors[2C]), MC3 MID ULLLURLR  OSEM PDs (see SUSH2A_ADC_DAC_BIO[1D]), MC3 MID ULLLURLR  SFVMON (see SUSAUXH2_ADC_Monitors[2C])

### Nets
HAM2-211: C57.D25F C58.D25M(Vac._Side)
HAM2_212A: C54.uD9M(UL) C55.uD9(Q1)
HAM2_212B: C54.uD9M(LL) C55.uD9(Q2)
HAM2_212C: C54.uD9M(UR) C55.uD9(Q3)
HAM2_212D: C54.uD9M(LR) C55.uD9(Q4)
HAM2_212E: C55.D25M(Flange) C57.D25M
HAM2_213: C63.D25F C64.D25M(Vac._Side)
HAM2_214A: C60.uD9M(UL) C61.uD9(Q1)
HAM2_214B: C60.uD9M(LL) C61.uD9(Q2)
HAM2_214C: C60.uD9M(UR) C61.uD9(Q3)
HAM2_214D: C60.uD9M(LR) C61.uD9(Q4)
HAM2_214E: C61.D25M(Flange) C63.D25M
SUS_HAM2_025: C56.D25F(To_Vacuum_Chamber) C58.D25M(Air_Side)
SUS_HAM2_026: C62.D25F(To_Vacuum_Chamber) C64.D25M(Air_Side)
SUS_HAM2_027: C56.D25M(Monitors_to_ADC) C59.D25F(PD_in_From_Sat)
SUS_HAM2_028: C56.D15M(Coil_Drive_Interface) C59.D15F(Coil_Out_to_Sat)
SUS_HAM2_029: C62.D25M(Monitors_to_ADC) C65.D25F(PD_in_From_Sat)
SUS_HAM2_030: C62.D15M(Coil_Drive_Interface) C65.D15F(Coil_Out_to_Sat)
SUS_HAM2_059: C59.D25F(Relay_Monitors) ; port MC3 MID ULLLURLR  BIO IN
SUS_HAM2_060: C59.D25M(Relay_Commands) ; port MC3 MID ULLLURLR  BIO OUT
SUS_HAM2_061: C65.D25F(Relay_Monitors) ; port MC3 BOT ULLLURLR  BIO IN
SUS_HAM2_062: C65.D25M(Relay_Commands) ; port MC3 BOT ULLLURLR  BIO OUT
SUS_HAM2_082: C59.D9F(PD_Out_to_AA) ; port MC3 MID ULLLURLR  OSEM PDs
SUS_HAM2_083: C65.D9F(PD_Out_to_AA) ; port MC3 BOT ULLLURLR  OSEM PDs
SUS_HAM2_105: C59.D9M(Drive_Input) ; port MC3 MID ULLLURLR  Coil Drive
SUS_HAM2_106: C65.D9M(Drive_Input) ; port MC3 BOT ULLLURLR  Coil Drive
SUS_HAM2_143: C59.D9F(Noise_Monitor) ; port MC3 MID ULLLURLR  NOISEMON
SUS_HAM2_144: C65.D9F(Noise_Monitor) ; port MC3 BOT ULLLURLR  NOISEMON
SUS_HAM2_145: C59.D25M(VI_&_RMS_Monitor) ; port MC3 MID ULLLURLR  SFVMON
SUS_HAM2_146: C65.D25M(VI_&_RMS_Monitor) ; port MC3 BOT ULLLURLR  SFVMON

Not connected (* = marked no-connect by the designer): C56 Conec 3(DC_±18v)* D37F(Local_Diagnostics)*; C59 Conec 3(DC_±18v)*; C62 Conec 3(DC_±18v)* D37F(Local_Diagnostics)*; C65 Conec 3(DC_±18v)*

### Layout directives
Length: 60in; DCC: Connector J1(E): HAM2_212E, HAM2_214E
Length: 52ft; DCC: D2100464: SUS_HAM2_025, SUS_HAM2_026
Length: 5ft; DCC: D2100753: SUS_HAM2_082, SUS_HAM2_083, SUS_HAM2_143, SUS_HAM2_144
Length: 5ft; DCC: D2100754: SUS_HAM2_105, SUS_HAM2_106
Length: 5ft; DCC: D2100755: SUS_HAM2_145, SUS_HAM2_146
Length: 60in; DCC: Connector J5(D): HAM2_212D, HAM2_214D
Length: 60in; DCC: Connector J4(C): HAM2_212C, HAM2_214C
Length: 60in; DCC: Connector J3(B): HAM2_212B, HAM2_214B
Length: 60in; DCC: Connector J2(A): HAM2_212A, HAM2_214A
Length: 66ft; DCC: D2100747: SUS_HAM2_028, SUS_HAM2_030
Length: 66ft; DCC: D2100748: SUS_HAM2_027, SUS_HAM2_029
Length: 5ft; DCC: D1003058: SUS_HAM2_059, SUS_HAM2_061
Length: 5ft; DCC: D1003057: SUS_HAM2_060, SUS_HAM2_062
Length: 9ft; DCC: D1000225: HAM2-211, HAM2_213

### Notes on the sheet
- MC3 MIDDLE MASS
- MC3 BOTTOM MASS

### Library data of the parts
C54 C60 = 4-AOSEM Array UL-Type: as C42 on sheet MC1 Middle and Bottom
C55 C61 = D1000234 D25 Quadrapus: as C26 on sheet MC1 and MC3 Top Masses
C56 C62 = Satellite Amplifier UK D0900900: System: SUS; Serial: Sxxxxxxx
C57 = D1001346-3 2nd Cable Bracket: as C86 on sheet PRM and PR3 Top Masses
C58 C64 = VacFeedD25: as C29 on sheet MC1 and MC3 Top Masses
C59 C65 = CD Triple Acq D090006: System: SUS; Serial: Sxxxxxxx
C63 = D1001346-3 1st Cable Bracket: as C33 on sheet MC1 and MC3 Top Masses

## Sheet PRM Middle and Bottom.SchDoc: PRM Middle and Bottom
size C; Organization: LIGO Laboratory; Address1: California Institute of Technology; Address2: Massachusetts Institute of Technology; DocumentNumber: D0902810; Revision: v11; SheetNumber: 5; SheetTotal: 14; Engineer: J.Kissel/L.Sánchez
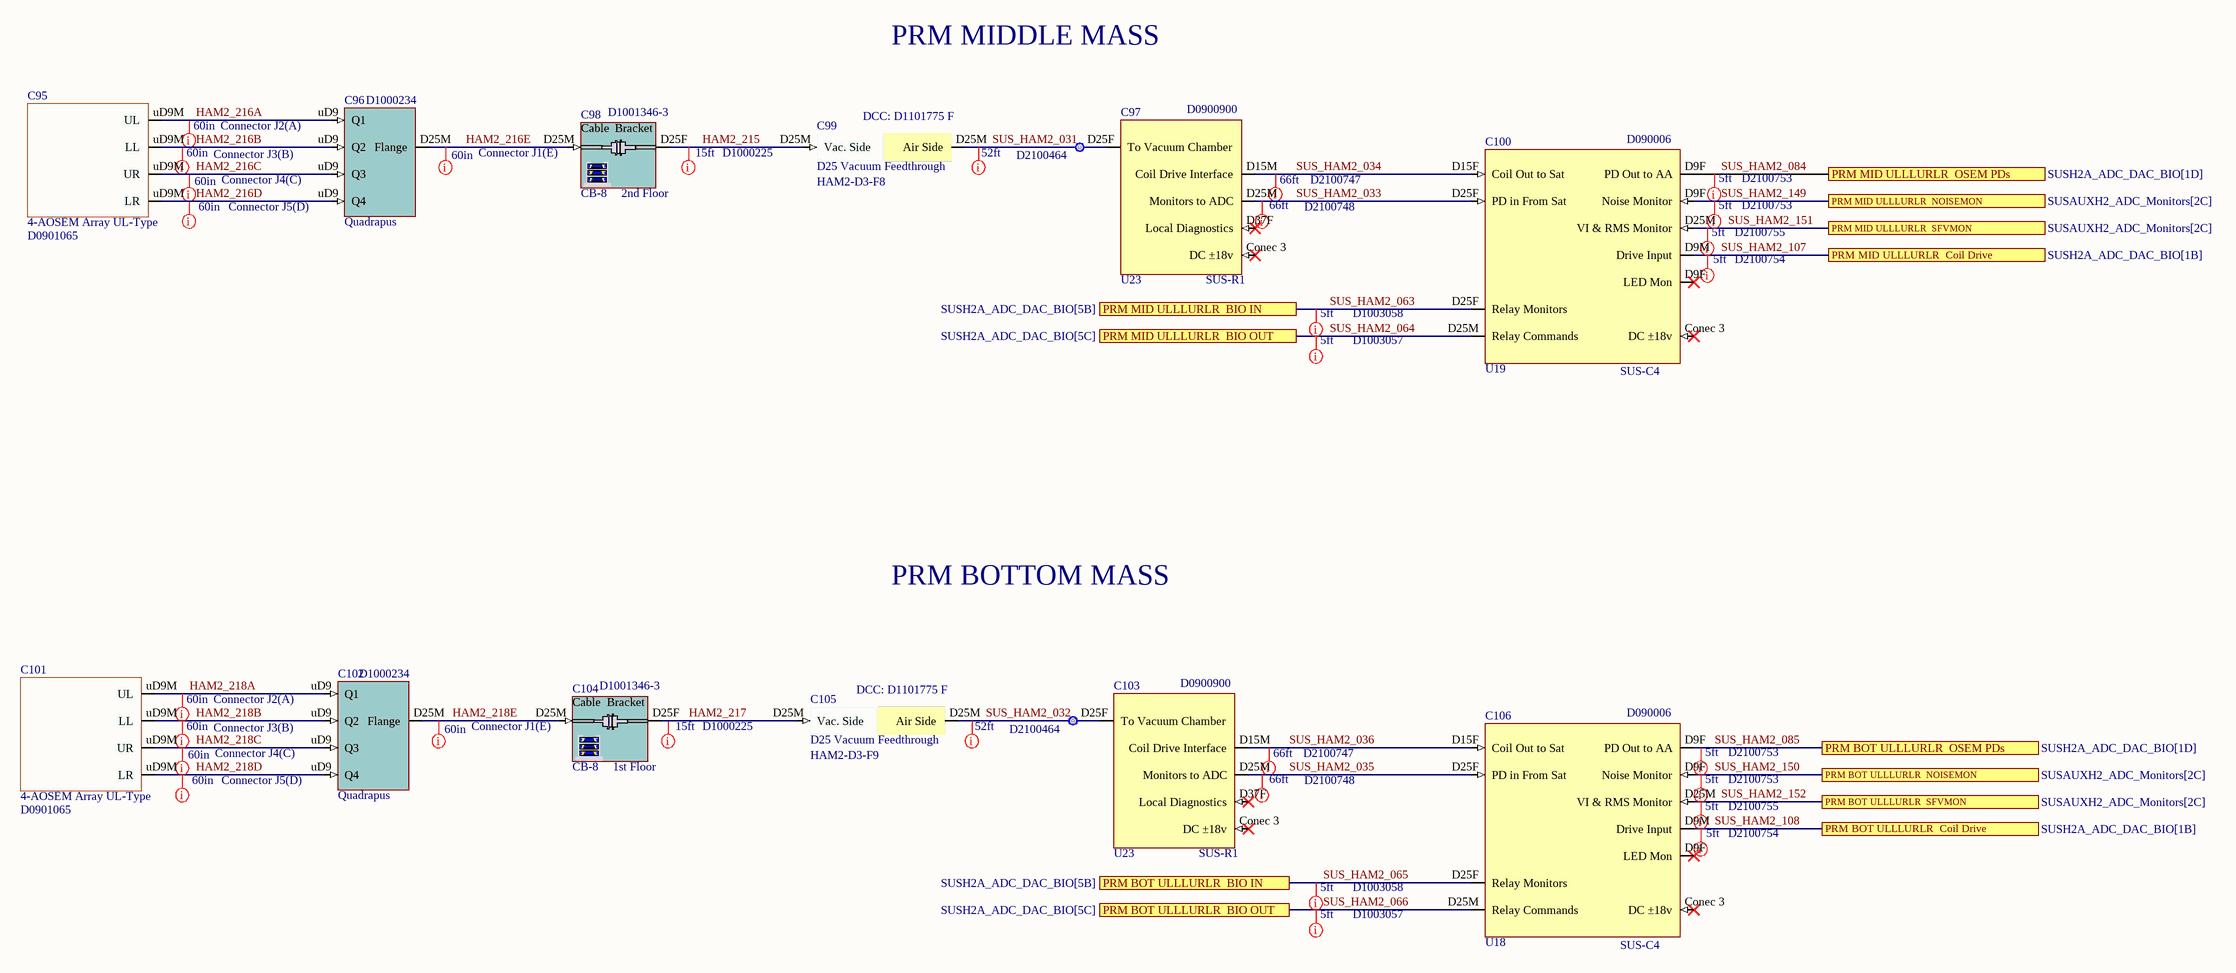
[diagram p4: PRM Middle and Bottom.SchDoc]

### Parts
C95  4-AOSEM Array UL-Type  DCC: D0901065
C96  Quadrapus  DCC: D1000234
C97  Slot: U23  Rack: SUS-R1  DCC: D0900900  (hidden comment: Satellite Amplifier UK D0900900)
C98  Rack: CB-8  DCC: D1001346-3  Slot: 2nd Floor  (hidden comment: D1001346-3 2nd Cable Bracket)
C99  D25 Vacuum Feedthrough  value HAM2-D3-F8  DCC: D1101775 F
C100  Slot: U19  Rack: SUS-C4  DCC: D090006  (hidden comment: CD Triple Acq D090006)
C101  4-AOSEM Array UL-Type  DCC: D0901065
C102  Quadrapus  DCC: D1000234
C103  Slot: U23  Rack: SUS-R1  DCC: D0900900  (hidden comment: Satellite Amplifier UK D0900900)
C104  Rack: CB-8  Slot: 1st Floor  DCC: D1001346-3  (hidden comment: D1001346-3 1st Cable Bracket)
C105  D25 Vacuum Feedthrough  value HAM2-D3-F9  DCC: D1101775 F
C106  Slot: U18  Rack: SUS-C4  DCC: D090006  (hidden comment: CD Triple Acq D090006)

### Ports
PRM BOT ULLLURLR  BIO IN (see SUSH2A_ADC_DAC_BIO[5B]), PRM BOT ULLLURLR  BIO OUT (see SUSH2A_ADC_DAC_BIO[5C]), PRM BOT ULLLURLR  Coil Drive (see SUSH2A_ADC_DAC_BIO[1B]), PRM BOT ULLLURLR  NOISEMON (see SUSAUXH2_ADC_Monitors[2C]), PRM BOT ULLLURLR  OSEM PDs (see SUSH2A_ADC_DAC_BIO[1D]), PRM BOT ULLLURLR  SFVMON (see SUSAUXH2_ADC_Monitors[2C]), PRM MID ULLLURLR  BIO IN (see SUSH2A_ADC_DAC_BIO[5B]), PRM MID ULLLURLR  BIO OUT (see SUSH2A_ADC_DAC_BIO[5C]), PRM MID ULLLURLR  Coil Drive (see SUSH2A_ADC_DAC_BIO[1B]), PRM MID ULLLURLR  NOISEMON (see SUSAUXH2_ADC_Monitors[2C]), PRM MID ULLLURLR  OSEM PDs (see SUSH2A_ADC_DAC_BIO[1D]), PRM MID ULLLURLR  SFVMON (see SUSAUXH2_ADC_Monitors[2C])

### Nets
HAM2_215: C98.D25F C99.D25M(Vac._Side)
HAM2_216A: C95.uD9M(UL) C96.uD9(Q1)
HAM2_216B: C95.uD9M(LL) C96.uD9(Q2)
HAM2_216C: C95.uD9M(UR) C96.uD9(Q3)
HAM2_216D: C95.uD9M(LR) C96.uD9(Q4)
HAM2_216E: C96.D25M(Flange) C98.D25M
HAM2_217: C104.D25F C105.D25M(Vac._Side)
HAM2_218A: C101.uD9M(UL) C102.uD9(Q1)
HAM2_218B: C101.uD9M(LL) C102.uD9(Q2)
HAM2_218C: C101.uD9M(UR) C102.uD9(Q3)
HAM2_218D: C101.uD9M(LR) C102.uD9(Q4)
HAM2_218E: C102.D25M(Flange) C104.D25M
SUS_HAM2_031: C97.D25F(To_Vacuum_Chamber) C99.D25M(Air_Side)
SUS_HAM2_032: C103.D25F(To_Vacuum_Chamber) C105.D25M(Air_Side)
SUS_HAM2_033: C97.D25M(Monitors_to_ADC) C100.D25F(PD_in_From_Sat)
SUS_HAM2_034: C97.D15M(Coil_Drive_Interface) C100.D15F(Coil_Out_to_Sat)
SUS_HAM2_035: C103.D25M(Monitors_to_ADC) C106.D25F(PD_in_From_Sat)
SUS_HAM2_036: C103.D15M(Coil_Drive_Interface) C106.D15F(Coil_Out_to_Sat)
SUS_HAM2_063: C100.D25F(Relay_Monitors) ; port PRM MID ULLLURLR  BIO IN
SUS_HAM2_064: C100.D25M(Relay_Commands) ; port PRM MID ULLLURLR  BIO OUT
SUS_HAM2_065: C106.D25F(Relay_Monitors) ; port PRM BOT ULLLURLR  BIO IN
SUS_HAM2_066: C106.D25M(Relay_Commands) ; port PRM BOT ULLLURLR  BIO OUT
SUS_HAM2_084: C100.D9F(PD_Out_to_AA) ; port PRM MID ULLLURLR  OSEM PDs
SUS_HAM2_085: C106.D9F(PD_Out_to_AA) ; port PRM BOT ULLLURLR  OSEM PDs
SUS_HAM2_107: C100.D9M(Drive_Input) ; port PRM MID ULLLURLR  Coil Drive
SUS_HAM2_108: C106.D9M(Drive_Input) ; port PRM BOT ULLLURLR  Coil Drive
SUS_HAM2_149: C100.D9F(Noise_Monitor) ; port PRM MID ULLLURLR  NOISEMON
SUS_HAM2_150: C106.D9F(Noise_Monitor) ; port PRM BOT ULLLURLR  NOISEMON
SUS_HAM2_151: C100.D25M(VI_&_RMS_Monitor) ; port PRM MID ULLLURLR  SFVMON
SUS_HAM2_152: C106.D25M(VI_&_RMS_Monitor) ; port PRM BOT ULLLURLR  SFVMON

Not connected (* = marked no-connect by the designer): C97 Conec 3(DC_±18v)* D37F(Local_Diagnostics)*; C100 Conec 3(DC_±18v)*; C103 Conec 3(DC_±18v)* D37F(Local_Diagnostics)*; C106 Conec 3(DC_±18v)*

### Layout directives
Length: 52ft; DCC: D2100464: SUS_HAM2_031, SUS_HAM2_032
Length: 5ft; DCC: D2100753: SUS_HAM2_084, SUS_HAM2_085, SUS_HAM2_149, SUS_HAM2_150
Length: 5ft; DCC: D2100754: SUS_HAM2_107, SUS_HAM2_108
Length: 5ft; DCC: D2100755: SUS_HAM2_151, SUS_HAM2_152
Length: 60in; DCC: Connector J5(D): HAM2_216D, HAM2_218D
Length: 60in; DCC: Connector J4(C): HAM2_216C, HAM2_218C
Length: 60in; DCC: Connector J3(B): HAM2_216B, HAM2_218B
Length: 60in; DCC: Connector J2(A): HAM2_216A, HAM2_218A
Length: 66ft; DCC: D2100747: SUS_HAM2_034, SUS_HAM2_036
Length: 66ft; DCC: D2100748: SUS_HAM2_033, SUS_HAM2_035
Length: 5ft; DCC: D1003058: SUS_HAM2_063, SUS_HAM2_065
Length: 5ft; DCC: D1003057: SUS_HAM2_064, SUS_HAM2_066
Length: 15ft; DCC: D1000225: HAM2_215, HAM2_217
Length: 60in; DCC: Connector J1(E): HAM2_216E, HAM2_218E

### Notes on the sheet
- PRM MIDDLE MASS
- PRM BOTTOM MASS

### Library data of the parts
C95 C101 = 4-AOSEM Array UL-Type: as C42 on sheet MC1 Middle and Bottom
C96 C102 = D1000234 D25 Quadrapus: as C26 on sheet MC1 and MC3 Top Masses
C97 C103 = Satellite Amplifier UK D0900900: System: SUS; Serial: Sxxxxxxx
C98 = D1001346-3 2nd Cable Bracket: as C86 on sheet PRM and PR3 Top Masses
C99 C105 = VacFeedD25: as C29 on sheet MC1 and MC3 Top Masses
C100 C106 = CD Triple Acq D090006: System: SUS; Serial: Sxxxxxxx
C104 = D1001346-3 1st Cable Bracket: as C33 on sheet MC1 and MC3 Top Masses

## Sheet PR3 Middle and Bottom.SchDoc: PR3 Middle and Bottom/OpLev
size C; Organization: LIGO Laboratory; Address1: California Institute of Technology; Address2: Massachusetts Institute of Technology; DocumentNumber: D0902810; Revision: v11; SheetNumber: 6; SheetTotal: 14; Engineer: J.Kissel/L.Sánchez
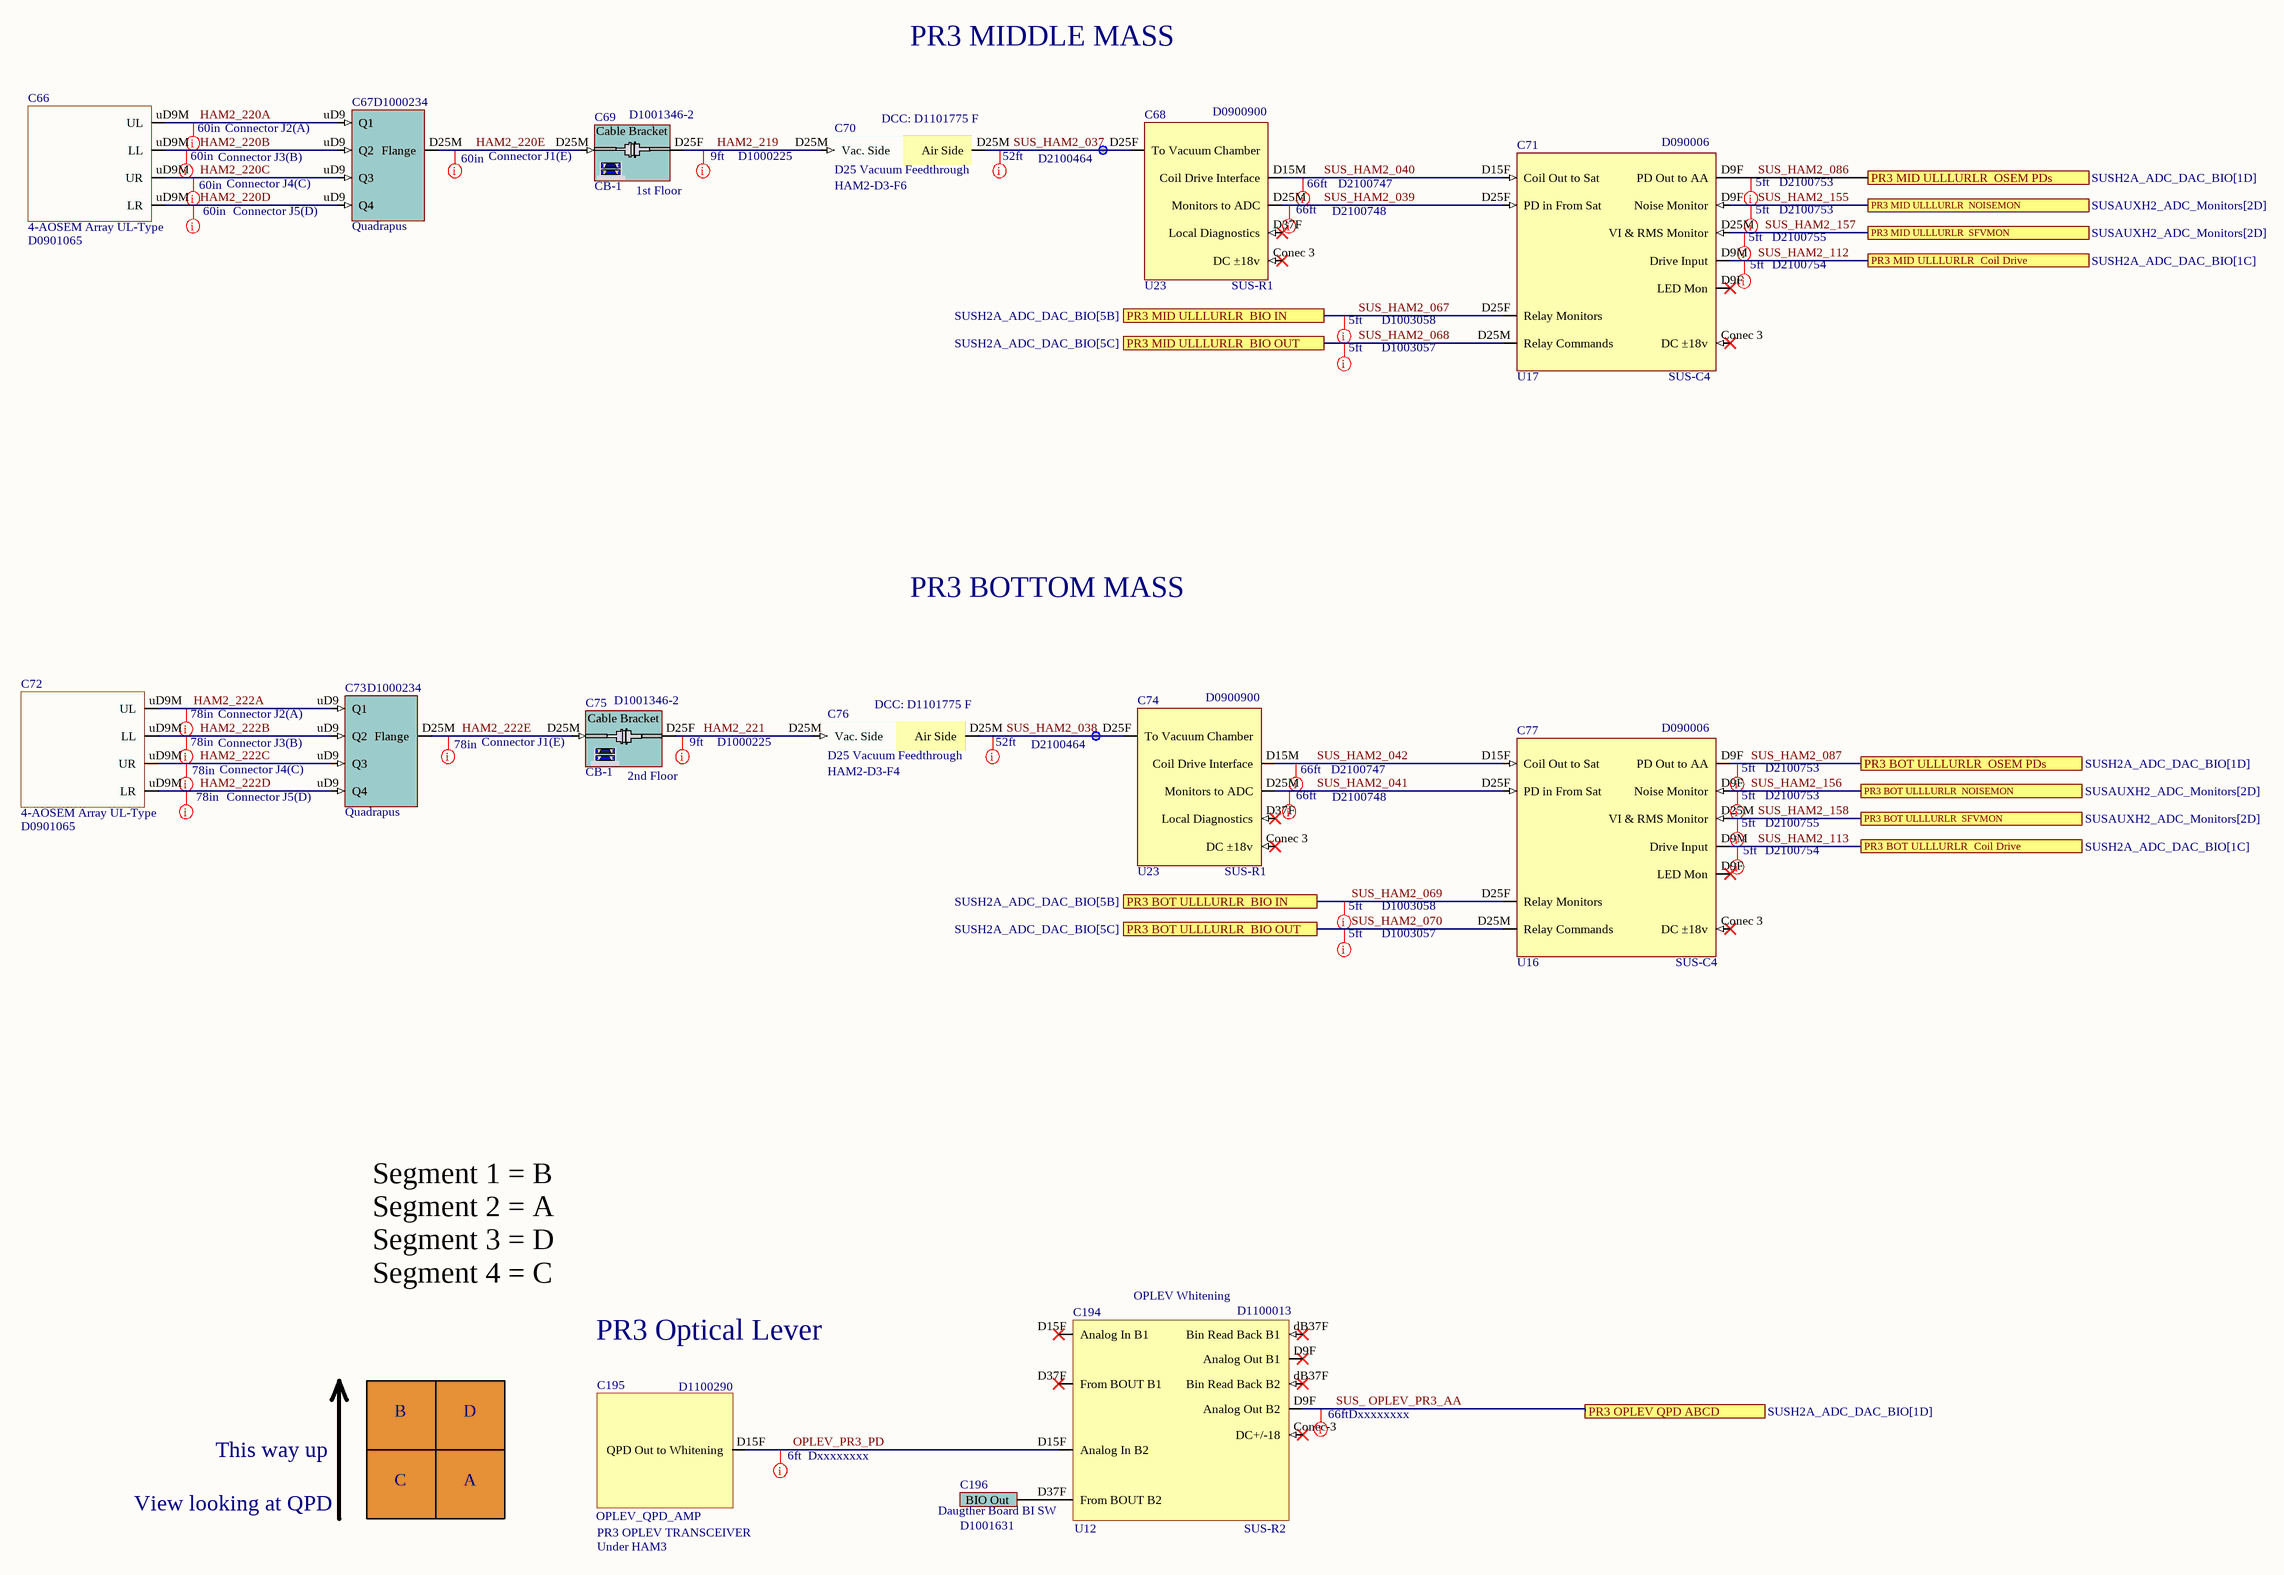
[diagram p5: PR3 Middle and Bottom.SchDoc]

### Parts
C66  4-AOSEM Array UL-Type  DCC: D0901065
C67  Quadrapus  DCC: D1000234
C68  Slot: U23  Rack: SUS-R1  DCC: D0900900  (hidden comment: Satellite Amplifier UK D0900900)
C69  Rack: CB-1  Slot: 1st Floor  DCC: D1001346-2  (hidden comment: Cable Bracket)
C70  D25 Vacuum Feedthrough  value HAM2-D3-F6  DCC: D1101775 F
C71  Slot: U17  Rack: SUS-C4  DCC: D090006  (hidden comment: CD Triple Acq D090006)
C72  4-AOSEM Array UL-Type  DCC: D0901065
C73  Quadrapus  DCC: D1000234
C74  Slot: U23  Rack: SUS-R1  DCC: D0900900  (hidden comment: Satellite Amplifier UK D0900900)
C75  Rack: CB-1  Slot: 2nd Floor  DCC: D1001346-2  (hidden comment: Cable Bracket)
C76  D25 Vacuum Feedthrough  value HAM2-D3-F4  DCC: D1101775 F
C77  Slot: U16  Rack: SUS-C4  DCC: D090006  (hidden comment: CD Triple Acq D090006)
C194  Rack: SUS-R2  DCC: D1100013  Parameter: OPLEV Whitening  Slot: U12  (hidden comment: 8CH OPLEV Whitening)
C195  Slot: Under HAM3  Rack: PR3 OPLEV TRANSCEIVER  DCC: D1100290  Parameter: OPLEV_QPD_AMP  (hidden comment: Optical Level QPD Amp)
C196  Daugther Board BI SW

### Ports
PR3 BOT ULLLURLR  BIO IN (see SUSH2A_ADC_DAC_BIO[5B]), PR3 BOT ULLLURLR  BIO OUT (see SUSH2A_ADC_DAC_BIO[5C]), PR3 BOT ULLLURLR  Coil Drive (see SUSH2A_ADC_DAC_BIO[1C]), PR3 BOT ULLLURLR  NOISEMON (see SUSAUXH2_ADC_Monitors[2D]), PR3 BOT ULLLURLR  OSEM PDs (see SUSH2A_ADC_DAC_BIO[1D]), PR3 BOT ULLLURLR  SFVMON (see SUSAUXH2_ADC_Monitors[2D]), PR3 MID ULLLURLR  BIO IN (see SUSH2A_ADC_DAC_BIO[5B]), PR3 MID ULLLURLR  BIO OUT (see SUSH2A_ADC_DAC_BIO[5C]), PR3 MID ULLLURLR  Coil Drive (see SUSH2A_ADC_DAC_BIO[1C]), PR3 MID ULLLURLR  NOISEMON (see SUSAUXH2_ADC_Monitors[2D]), PR3 MID ULLLURLR  OSEM PDs (see SUSH2A_ADC_DAC_BIO[1D]), PR3 MID ULLLURLR  SFVMON (see SUSAUXH2_ADC_Monitors[2D]), PR3 OPLEV QPD ABCD (see SUSH2A_ADC_DAC_BIO[1D])

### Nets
HAM2_219: C69.D25F C70.D25M(Vac._Side)
HAM2_220A: C66.uD9M(UL) C67.uD9(Q1)
HAM2_220B: C66.uD9M(LL) C67.uD9(Q2)
HAM2_220C: C66.uD9M(UR) C67.uD9(Q3)
HAM2_220D: C66.uD9M(LR) C67.uD9(Q4)
HAM2_220E: C67.D25M(Flange) C69.D25M
HAM2_221: C75.D25F C76.D25M(Vac._Side)
HAM2_222A: C72.uD9M(UL) C73.uD9(Q1)
HAM2_222B: C72.uD9M(LL) C73.uD9(Q2)
HAM2_222C: C72.uD9M(UR) C73.uD9(Q3)
HAM2_222D: C72.uD9M(LR) C73.uD9(Q4)
HAM2_222E: C73.D25M(Flange) C75.D25M
OPLEV_PR3_PD: C194.D15F(Analog_In_B1) C195.D15F(QPD_Out_to_Whitening)
SUS_ OPLEV_PR3_AA: C194.D9F(Analog_Out_B1) ; port PR3 OPLEV QPD ABCD
SUS_HAM2_037: C68.D25F(To_Vacuum_Chamber) C70.D25M(Air_Side)
SUS_HAM2_038: C74.D25F(To_Vacuum_Chamber) C76.D25M(Air_Side)
SUS_HAM2_039: C68.D25M(Monitors_to_ADC) C71.D25F(PD_in_From_Sat)
SUS_HAM2_040: C68.D15M(Coil_Drive_Interface) C71.D15F(Coil_Out_to_Sat)
SUS_HAM2_041: C74.D25M(Monitors_to_ADC) C77.D25F(PD_in_From_Sat)
SUS_HAM2_042: C74.D15M(Coil_Drive_Interface) C77.D15F(Coil_Out_to_Sat)
SUS_HAM2_067: C71.D25F(Relay_Monitors) ; port PR3 MID ULLLURLR  BIO IN
SUS_HAM2_068: C71.D25M(Relay_Commands) ; port PR3 MID ULLLURLR  BIO OUT
SUS_HAM2_069: C77.D25F(Relay_Monitors) ; port PR3 BOT ULLLURLR  BIO IN
SUS_HAM2_070: C77.D25M(Relay_Commands) ; port PR3 BOT ULLLURLR  BIO OUT
SUS_HAM2_086: C71.D9F(PD_Out_to_AA) ; port PR3 MID ULLLURLR  OSEM PDs
SUS_HAM2_087: C77.D9F(PD_Out_to_AA) ; port PR3 BOT ULLLURLR  OSEM PDs
SUS_HAM2_112: C71.D9M(Drive_Input) ; port PR3 MID ULLLURLR  Coil Drive
SUS_HAM2_113: C77.D9M(Drive_Input) ; port PR3 BOT ULLLURLR  Coil Drive
SUS_HAM2_155: C71.D9F(Noise_Monitor) ; port PR3 MID ULLLURLR  NOISEMON
SUS_HAM2_156: C77.D9F(Noise_Monitor) ; port PR3 BOT ULLLURLR  NOISEMON
SUS_HAM2_157: C71.D25M(VI_&_RMS_Monitor) ; port PR3 MID ULLLURLR  SFVMON
SUS_HAM2_158: C77.D25M(VI_&_RMS_Monitor) ; port PR3 BOT ULLLURLR  SFVMON
NetC194_D37F: C194.D37F(From_BOUT_B1) C196.D37M(BIO_Out)

Not connected (* = marked no-connect by the designer): C68 Conec 3(DC_±18v)* D37F(Local_Diagnostics)*; C71 Conec 3(DC_±18v)*; C74 Conec 3(DC_±18v)* D37F(Local_Diagnostics)*; C77 Conec 3(DC_±18v)*; C194 Conec-3(DC+/-18)* dB37F(Bin_Read_Back_B1)*

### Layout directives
Length: 52ft; DCC: D2100464: SUS_HAM2_037, SUS_HAM2_038
Length: 5ft; DCC: D2100753: SUS_HAM2_086, SUS_HAM2_087, SUS_HAM2_155, SUS_HAM2_156
Length: 5ft; DCC: D2100754: SUS_HAM2_112, SUS_HAM2_113
Length: 5ft; DCC: D2100755: SUS_HAM2_157, SUS_HAM2_158
Length: 60in; DCC: Connector J5(D): HAM2_220D
Length: 60in; DCC: Connector J4(C): HAM2_220C
Length: 60in; DCC: Connector J3(B): HAM2_220B
Length: 60in; DCC: Connector J2(A): HAM2_220A
Length: 66ft; DCC: D2100747: SUS_HAM2_040, SUS_HAM2_042
Length: 66ft; DCC: D2100748: SUS_HAM2_039, SUS_HAM2_041
Length: 5ft; DCC: D1003058: SUS_HAM2_067, SUS_HAM2_069
Length: 5ft; DCC: D1003057: SUS_HAM2_068, SUS_HAM2_070
Length: 9ft; DCC: D1000225: HAM2_219, HAM2_221
Length: 78in; DCC: Connector J5(D): HAM2_222D
Length: 78in; DCC: Connector J4(C): HAM2_222C
Length: 78in; DCC: Connector J3(B): HAM2_222B
Length: 78in; DCC: Connector J2(A): HAM2_222A
Length: 60in; DCC: Connector J1(E): HAM2_220E
Length: 78in; DCC: Connector J1(E): HAM2_222E
Length: 66ft; DCC: Dxxxxxxxx: SUS_ OPLEV_PR3_AA
Length: 6ft; DCC: Dxxxxxxxx: OPLEV_PR3_PD

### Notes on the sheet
- PR3 MIDDLE MASS
- PR3 BOTTOM MASS
- Segment 1 = B
  Segment 2 = A
  Segment 3 = D
  Segment 4 = C
- PR3 Optical Lever
- This way up
- B
- D
- View looking at QPD
- C
- A

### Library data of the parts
C66 C72 = 4-AOSEM Array UL-Type: as C42 on sheet MC1 Middle and Bottom
C67 C73 = D1000234 D25 Quadrapus: as C26 on sheet MC1 and MC3 Top Masses
C68 C74 = Satellite Amplifier UK D0900900: System: SUS; Serial: Sxxxxxxx
C69 = D1001346-2 1st Cable Bracket: as C28 on sheet MC1 and MC3 Top Masses
C70 C76 = VacFeedD25: as C29 on sheet MC1 and MC3 Top Masses
C71 C77 = CD Triple Acq D090006: System: SUS; Serial: Sxxxxxxx
C75 = D1001346-2 2nd Cable Bracket: D1001346-2 2/2 Cable Bracket for HAM Tables; Serial: Sxxxxxxx; System: SUS
C194 = OPLEV Whitening D1100013: System: SUS; Serial: Sxxxxxxx
C195 = Optical Lever QPD D1100290: Serial: Sxxxxxxxx
C196 = D1001631: Rack: SUS-R?; Serial: Sxxxxxxx; Slot: U?; System: SUS

## Sheet IM1_IM2_IM3_IM4_OSEMs.SchDoc: IM1, IM2, IM3, IM4
size C; Organization: LIGO Laboratory; Address1: California Institute of Technology; Address2: Massachusetts Institute of Technology; DocumentNumber: D0902810; Revision: v11; SheetNumber: 7; SheetTotal: 14; Engineer: J.Kissel/L.Sánchez
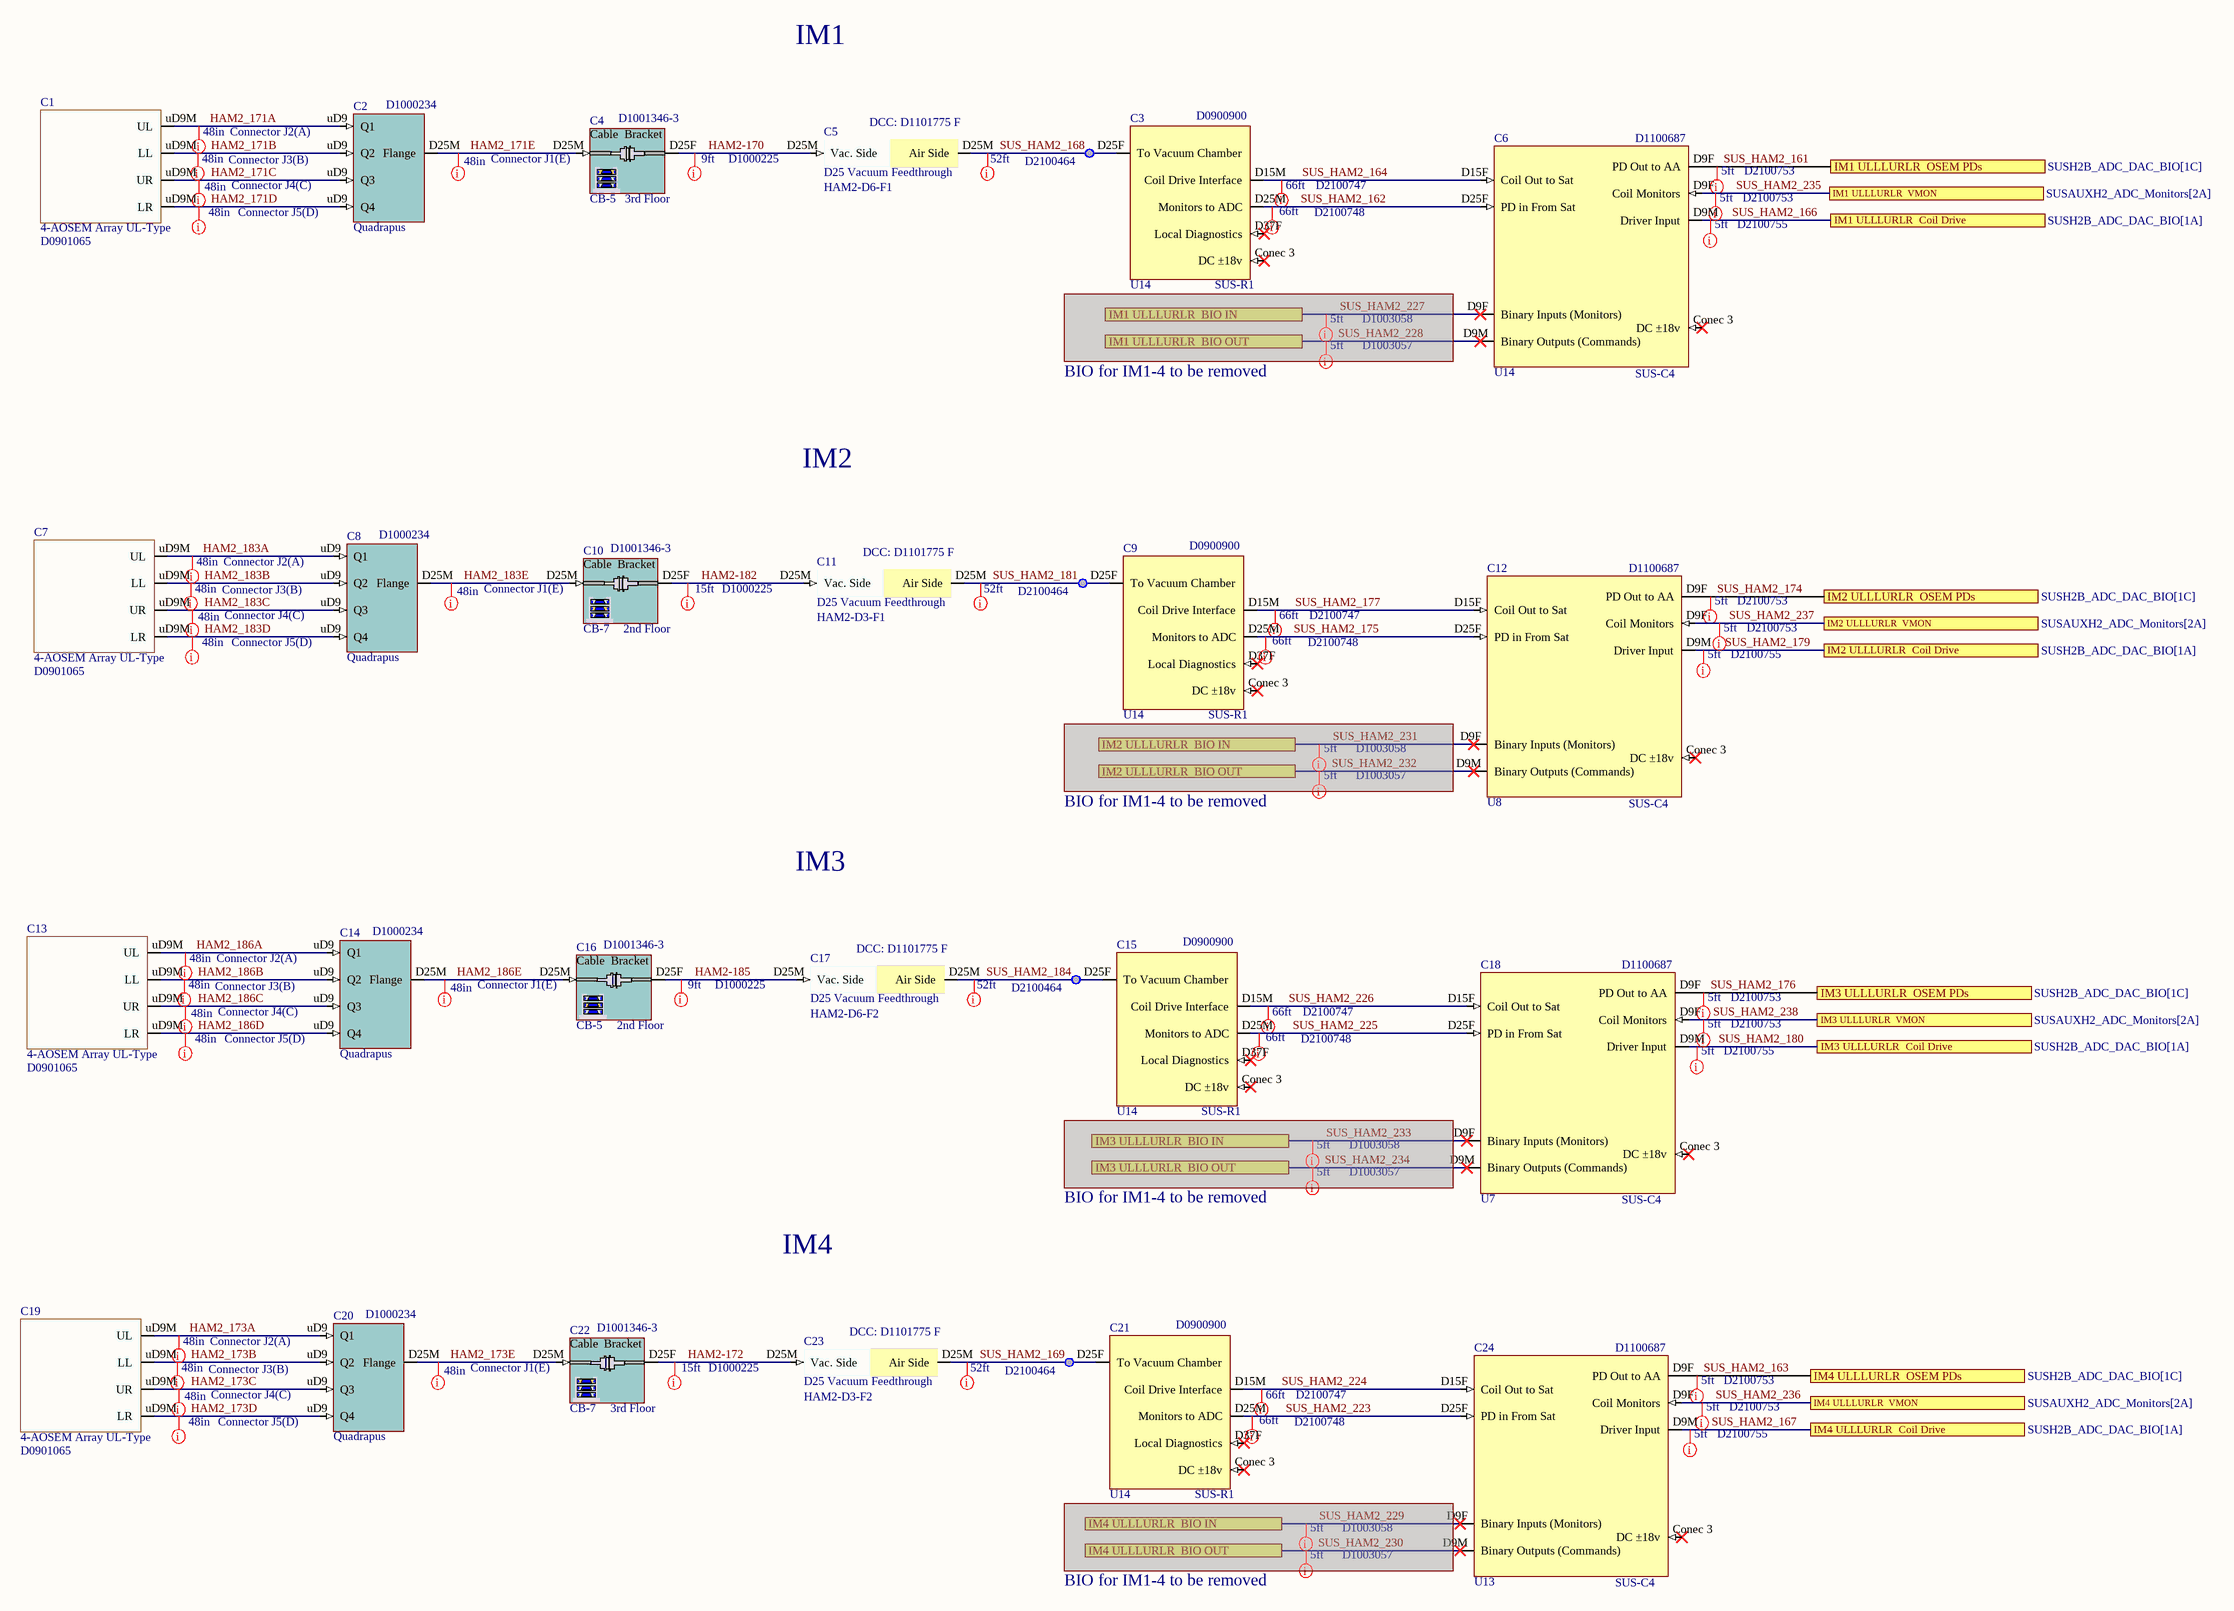
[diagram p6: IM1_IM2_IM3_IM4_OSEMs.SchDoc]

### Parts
C1  4-AOSEM Array UL-Type  DCC: D0901065
C2  Quadrapus  DCC: D1000234
C3  Slot: U14  Rack: SUS-R1  DCC: D0900900  (hidden comment: Satellite Amplifier UK D0900900)
C4  Rack: CB-5  DCC: D1001346-3  Slot: 3rd Floor  (hidden comment: D1001346-3 3rd Cable Bracket)
C5  D25 Vacuum Feedthrough  value HAM2-D6-F1  DCC: D1101775 F
C6  Slot: U14  Rack: SUS-C4  DCC: D1100687  (hidden comment: CD HAM-A D1100687)
C7  4-AOSEM Array UL-Type  DCC: D0901065
C8  Quadrapus  DCC: D1000234
C9  Slot: U14  Rack: SUS-R1  DCC: D0900900  (hidden comment: Satellite Amplifier UK D0900900)
C10  Rack: CB-7  DCC: D1001346-3  Slot: 2nd Floor  (hidden comment: D1001346-3 2nd Cable Bracket)
C11  D25 Vacuum Feedthrough  value HAM2-D3-F1  DCC: D1101775 F
C12  Slot: U8  Rack: SUS-C4  DCC: D1100687  (hidden comment: CD HAM-A D1100687)
C13  4-AOSEM Array UL-Type  DCC: D0901065
C14  Quadrapus  DCC: D1000234
C15  Slot: U14  Rack: SUS-R1  DCC: D0900900  (hidden comment: Satellite Amplifier UK D0900900)
C16  Rack: CB-5  DCC: D1001346-3  Slot: 2nd Floor  (hidden comment: D1001346-3 2nd Cable Bracket)
C17  D25 Vacuum Feedthrough  value HAM2-D6-F2  DCC: D1101775 F
C18  Slot: U7  Rack: SUS-C4  DCC: D1100687  (hidden comment: CD HAM-A D1100687)
C19  4-AOSEM Array UL-Type  DCC: D0901065
C20  Quadrapus  DCC: D1000234
C21  Slot: U14  Rack: SUS-R1  DCC: D0900900  (hidden comment: Satellite Amplifier UK D0900900)
C22  Rack: CB-7  DCC: D1001346-3  Slot: 3rd Floor  (hidden comment: D1001346-3 3rd Cable Bracket)
C23  D25 Vacuum Feedthrough  value HAM2-D3-F2  DCC: D1101775 F
C24  Slot: U13  Rack: SUS-C4  DCC: D1100687  (hidden comment: CD HAM-A D1100687)

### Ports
IM1 ULLLURLR  BIO IN, IM1 ULLLURLR  BIO OUT, IM1 ULLLURLR  Coil Drive (see SUSH2B_ADC_DAC_BIO[1A]), IM1 ULLLURLR  OSEM PDs (see SUSH2B_ADC_DAC_BIO[1C]), IM1 ULLLURLR  VMON (see SUSAUXH2_ADC_Monitors[2A]), IM2 ULLLURLR  BIO IN, IM2 ULLLURLR  BIO OUT, IM2 ULLLURLR  Coil Drive (see SUSH2B_ADC_DAC_BIO[1A]), IM2 ULLLURLR  OSEM PDs (see SUSH2B_ADC_DAC_BIO[1C]), IM2 ULLLURLR  VMON (see SUSAUXH2_ADC_Monitors[2A]), IM3 ULLLURLR  BIO IN, IM3 ULLLURLR  BIO OUT, IM3 ULLLURLR  Coil Drive (see SUSH2B_ADC_DAC_BIO[1A]), IM3 ULLLURLR  OSEM PDs (see SUSH2B_ADC_DAC_BIO[1C]), IM3 ULLLURLR  VMON (see SUSAUXH2_ADC_Monitors[2A]), IM4 ULLLURLR  BIO IN, IM4 ULLLURLR  BIO OUT, IM4 ULLLURLR  Coil Drive (see SUSH2B_ADC_DAC_BIO[1A]), IM4 ULLLURLR  OSEM PDs (see SUSH2B_ADC_DAC_BIO[1C]), IM4 ULLLURLR  VMON (see SUSAUXH2_ADC_Monitors[2A])

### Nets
HAM2-170: C4.D25F C5.D25M(Vac._Side)
HAM2-172: C22.D25F C23.D25M(Vac._Side)
HAM2-182: C10.D25F C11.D25M(Vac._Side)
HAM2-185: C16.D25F C17.D25M(Vac._Side)
HAM2_171A: C1.uD9M(UL) C2.uD9(Q1)
HAM2_171B: C1.uD9M(LL) C2.uD9(Q2)
HAM2_171C: C1.uD9M(UR) C2.uD9(Q3)
HAM2_171D: C1.uD9M(LR) C2.uD9(Q4)
HAM2_171E: C2.D25M(Flange) C4.D25M
HAM2_173A: C19.uD9M(UL) C20.uD9(Q1)
HAM2_173B: C19.uD9M(LL) C20.uD9(Q2)
HAM2_173C: C19.uD9M(UR) C20.uD9(Q3)
HAM2_173D: C19.uD9M(LR) C20.uD9(Q4)
HAM2_173E: C20.D25M(Flange) C22.D25M
HAM2_183A: C7.uD9M(UL) C8.uD9(Q1)
HAM2_183B: C7.uD9M(LL) C8.uD9(Q2)
HAM2_183C: C7.uD9M(UR) C8.uD9(Q3)
HAM2_183D: C7.uD9M(LR) C8.uD9(Q4)
HAM2_183E: C8.D25M(Flange) C10.D25M
HAM2_186A: C13.uD9M(UL) C14.uD9(Q1)
HAM2_186B: C13.uD9M(LL) C14.uD9(Q2)
HAM2_186C: C13.uD9M(UR) C14.uD9(Q3)
HAM2_186D: C13.uD9M(LR) C14.uD9(Q4)
HAM2_186E: C14.D25M(Flange) C16.D25M
SUS_HAM2_161: C6.D9F(PD_Out_to_AA) ; port IM1 ULLLURLR  OSEM PDs
SUS_HAM2_162: C3.D25M(Monitors_to_ADC) C6.D25F(PD_in_From_Sat)
SUS_HAM2_163: C24.D9F(PD_Out_to_AA) ; port IM4 ULLLURLR  OSEM PDs
SUS_HAM2_164: C3.D15M(Coil_Drive_Interface) C6.D15F(Coil_Out_to_Sat)
SUS_HAM2_166: C6.D9M(Binary_Outputs_(Commands)) ; port IM1 ULLLURLR  Coil Drive
SUS_HAM2_167: C24.D9M(Binary_Outputs_(Commands)) ; port IM4 ULLLURLR  Coil Drive
SUS_HAM2_168: C3.D25F(To_Vacuum_Chamber) C5.D25M(Air_Side)
SUS_HAM2_169: C21.D25F(To_Vacuum_Chamber) C23.D25M(Air_Side)
SUS_HAM2_174: C12.D9F(PD_Out_to_AA) ; port IM2 ULLLURLR  OSEM PDs
SUS_HAM2_175: C9.D25M(Monitors_to_ADC) C12.D25F(PD_in_From_Sat)
SUS_HAM2_176: C18.D9F(PD_Out_to_AA) ; port IM3 ULLLURLR  OSEM PDs
SUS_HAM2_177: C9.D15M(Coil_Drive_Interface) C12.D15F(Coil_Out_to_Sat)
SUS_HAM2_179: C12.D9M(Binary_Outputs_(Commands)) ; port IM2 ULLLURLR  Coil Drive
SUS_HAM2_180: C18.D9M(Binary_Outputs_(Commands)) ; port IM3 ULLLURLR  Coil Drive
SUS_HAM2_181: C9.D25F(To_Vacuum_Chamber) C11.D25M(Air_Side)
SUS_HAM2_184: C15.D25F(To_Vacuum_Chamber) C17.D25M(Air_Side)
SUS_HAM2_223: C21.D25M(Monitors_to_ADC) C24.D25F(PD_in_From_Sat)
SUS_HAM2_224: C21.D15M(Coil_Drive_Interface) C24.D15F(Coil_Out_to_Sat)
SUS_HAM2_225: C15.D25M(Monitors_to_ADC) C18.D25F(PD_in_From_Sat)
SUS_HAM2_226: C15.D15M(Coil_Drive_Interface) C18.D15F(Coil_Out_to_Sat)
SUS_HAM2_235: C6.D9F(Coil_Monitors) ; port IM1 ULLLURLR  VMON
SUS_HAM2_236: C24.D9F(Coil_Monitors) ; port IM4 ULLLURLR  VMON
SUS_HAM2_237: C12.D9F(Coil_Monitors) ; port IM2 ULLLURLR  VMON
SUS_HAM2_238: C18.D9F(Coil_Monitors) ; port IM3 ULLLURLR  VMON

Not connected (* = marked no-connect by the designer): C3 Conec 3(DC_±18v)* D37F(Local_Diagnostics)*; C6 Conec 3(DC_±18v)*; C9 Conec 3(DC_±18v)* D37F(Local_Diagnostics)*; C12 Conec 3(DC_±18v)*; C15 Conec 3(DC_±18v)* D37F(Local_Diagnostics)*; C18 Conec 3(DC_±18v)*; C21 Conec 3(DC_±18v)* D37F(Local_Diagnostics)*; C24 Conec 3(DC_±18v)*

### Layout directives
Length: 52ft; DCC: D2100464: SUS_HAM2_168, SUS_HAM2_169, SUS_HAM2_181, SUS_HAM2_184
Length: 5ft; DCC: D2100753: SUS_HAM2_161, SUS_HAM2_163, SUS_HAM2_174, SUS_HAM2_176, SUS_HAM2_235, SUS_HAM2_236, SUS_HAM2_237, SUS_HAM2_238
Length: 5ft; DCC: D2100755: SUS_HAM2_166, SUS_HAM2_167, SUS_HAM2_179, SUS_HAM2_180
Length: 48in; DCC: Connector J5(D): HAM2_171D, HAM2_173D, HAM2_183D, HAM2_186D
Length: 48in; DCC: Connector J4(C): HAM2_171C, HAM2_173C, HAM2_183C, HAM2_186C
Length: 48in; DCC: Connector J3(B): HAM2_171B, HAM2_173B, HAM2_183B, HAM2_186B
Length: 48in; DCC: Connector J2(A): HAM2_171A, HAM2_173A, HAM2_183A, HAM2_186A
Length: 66ft; DCC: D2100747: SUS_HAM2_164, SUS_HAM2_177, SUS_HAM2_224, SUS_HAM2_226
Length: 66ft; DCC: D2100748: SUS_HAM2_162, SUS_HAM2_175, SUS_HAM2_223, SUS_HAM2_225
Length: 5ft; DCC: D1003058: SUS_HAM2_161, SUS_HAM2_163, SUS_HAM2_174, SUS_HAM2_176
Length: 5ft; DCC: D1003057: SUS_HAM2_166, SUS_HAM2_167, SUS_HAM2_179, SUS_HAM2_180
Length: 48in; DCC: Connector J1(E): HAM2_171E, HAM2_173E, HAM2_183E, HAM2_186E
Length: 9ft; DCC: D1000225: HAM2-170, HAM2-185
Length: 15ft; DCC: D1000225: HAM2-172, HAM2-182

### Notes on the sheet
- IM1
- BIO for IM1-4 to be removed
- IM2
- IM3
- IM4

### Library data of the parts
C1 C7 C13 C19 = 4-AOSEM Array UL-Type: as C42 on sheet MC1 Middle and Bottom
C2 C8 C14 C20 = D1000234 D25 Quadrapus: as C26 on sheet MC1 and MC3 Top Masses
C3 C9 C15 C21 = Satellite Amplifier UK D0900900: System: SUS; Serial: Sxxxxxxx
C4 C22 = D1001346-3 3rd Cable Bracket: as C39 on sheet MC1 and MC3 Top Masses
C5 C11 C17 C23 = VacFeedD25: as C29 on sheet MC1 and MC3 Top Masses
C6 C12 C18 C24 = CD HAM-A D1100687: System: SUS; Serial: Sxxxxxxx
C10 C16 = D1001346-3 2nd Cable Bracket: as C86 on sheet PRM and PR3 Top Masses

## Sheet RM1_RM2.SchDoc: RM1 & RM2
size C; Organization: LIGO Laboratory; Address1: California Institute of Technology; Address2: Massachusetts Institute of Technology; DocumentNumber: D0902810; Revision: v11; SheetNumber: 8; SheetTotal: 14; Engineer: J.Kissel/L.Sánchez
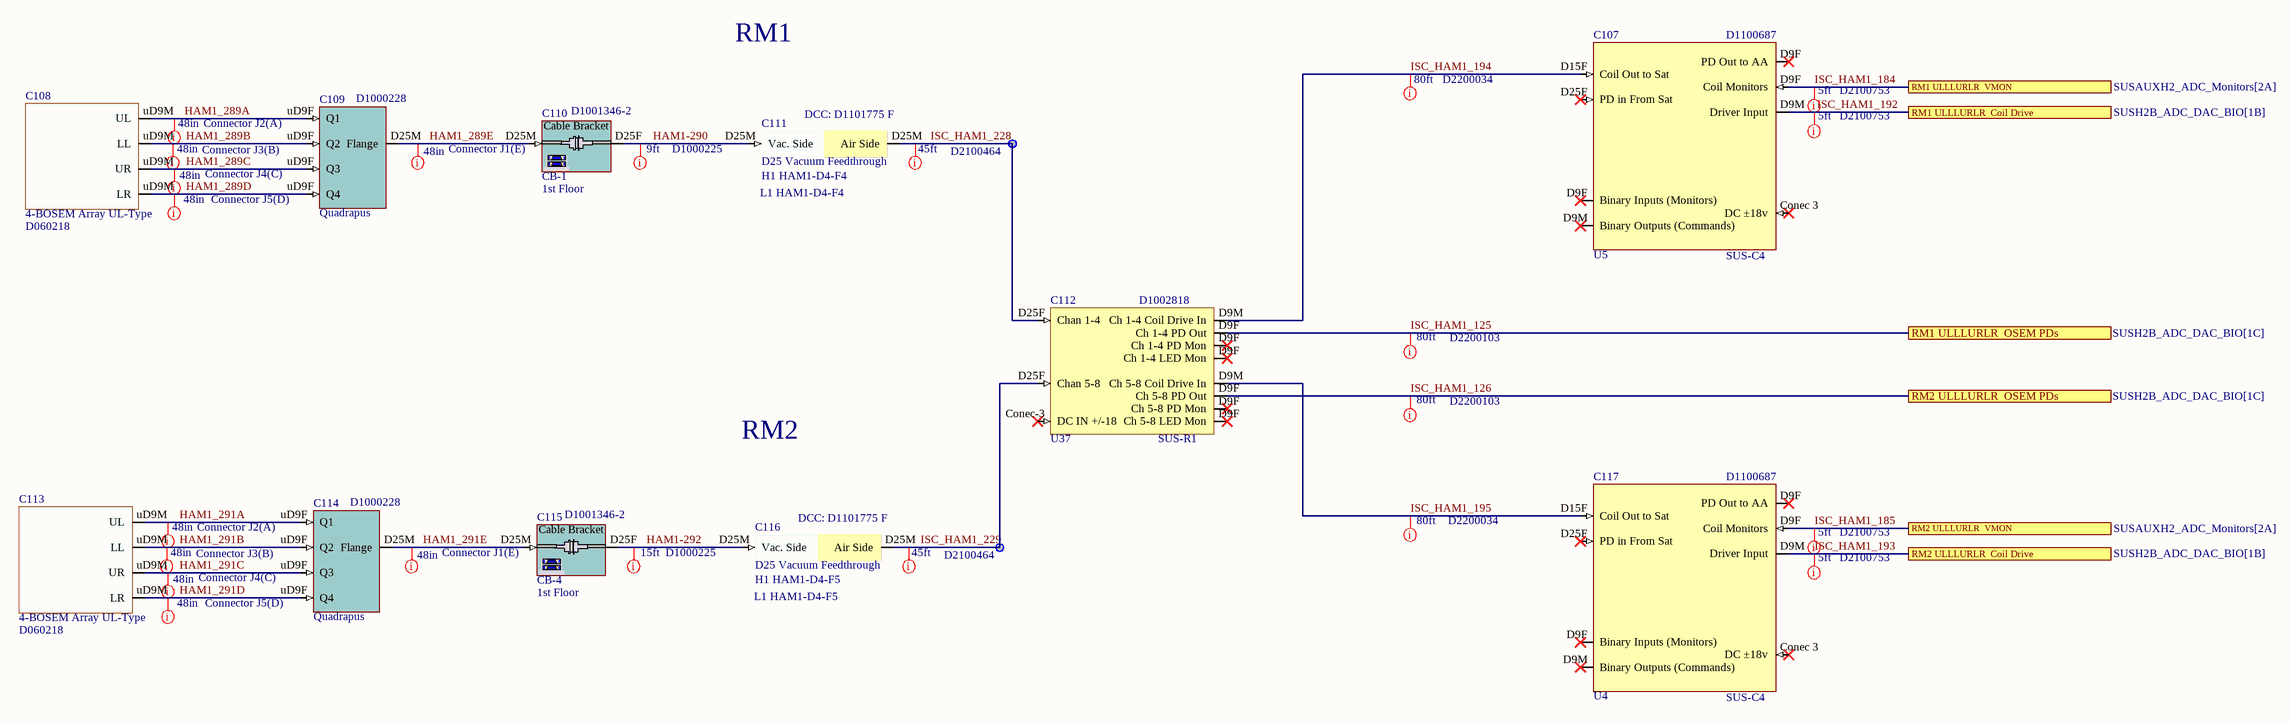
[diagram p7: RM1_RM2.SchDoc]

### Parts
C107  Slot: U5  Rack: SUS-C4  DCC: D1100687  (hidden comment: CD HAM-A D1100687)
C108  4-BOSEM Array UL-Type  DCC: D060218
C109  Quadrapus  DCC: D1000228
C110  Rack: CB-1  Slot: 1st Floor  DCC: D1001346-2  (hidden comment: Cable Bracket)
C111  D25 Vacuum Feedthrough  value H1 HAM1-D4-F4  DCC: D1101775 F
C112  DCC: D1002818  Rack: SUS-R1  Slot: U37  (hidden comment: Satellite Amplifier US D1002818 Dual)
C113  4-BOSEM Array UL-Type  DCC: D060218
C114  Quadrapus  DCC: D1000228
C115  Rack: CB-4  Slot: 1st Floor  DCC: D1001346-2  (hidden comment: Cable Bracket)
C116  D25 Vacuum Feedthrough  value H1 HAM1-D4-F5  DCC: D1101775 F
C117  Slot: U4  Rack: SUS-C4  DCC: D1100687  (hidden comment: CD HAM-A D1100687)

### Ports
RM1 ULLLURLR  Coil Drive (see SUSH2B_ADC_DAC_BIO[1B]), RM1 ULLLURLR  OSEM PDs (see SUSH2B_ADC_DAC_BIO[1C]), RM1 ULLLURLR  VMON (see SUSAUXH2_ADC_Monitors[2A]), RM2 ULLLURLR  Coil Drive (see SUSH2B_ADC_DAC_BIO[1B]), RM2 ULLLURLR  OSEM PDs (see SUSH2B_ADC_DAC_BIO[1C]), RM2 ULLLURLR  VMON (see SUSAUXH2_ADC_Monitors[2A])

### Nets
HAM1-290: C110.D25F C111.D25M(Vac._Side)
HAM1-292: C115.D25F C116.D25M(Vac._Side)
HAM1_289A: C108.uD9M(UL) C109.uD9F(Q1)
HAM1_289B: C108.uD9M(LL) C109.uD9F(Q2)
HAM1_289C: C108.uD9M(UR) C109.uD9F(Q3)
HAM1_289D: C108.uD9M(LR) C109.uD9F(Q4)
HAM1_289E: C109.D25M(Flange) C110.D25M
HAM1_291A: C113.uD9M(UL) C114.uD9F(Q1)
HAM1_291B: C113.uD9M(LL) C114.uD9F(Q2)
HAM1_291C: C113.uD9M(UR) C114.uD9F(Q3)
HAM1_291D: C113.uD9M(LR) C114.uD9F(Q4)
HAM1_291E: C114.D25M(Flange) C115.D25M
ISC_HAM1_125: C112.D9F(Ch_1-4_PD_Out) ; port RM1 ULLLURLR  OSEM PDs
ISC_HAM1_126: C112.D9F(Ch_5-8_PD_Out) ; port RM2 ULLLURLR  OSEM PDs
ISC_HAM1_184: C107.D9F(PD_Out_to_AA) ; port RM1 ULLLURLR  VMON
ISC_HAM1_185: C117.D9F(PD_Out_to_AA) ; port RM2 ULLLURLR  VMON
ISC_HAM1_192: C107.D9M(Binary_Outputs_(Commands)) ; port RM1 ULLLURLR  Coil Drive
ISC_HAM1_193: C117.D9M(Binary_Outputs_(Commands)) ; port RM2 ULLLURLR  Coil Drive
ISC_HAM1_194: C107.D15F(Coil_Out_to_Sat) C112.D9M(Ch_1-4_Coil_Drive_In)
ISC_HAM1_195: C112.D9M(Ch_5-8_Coil_Drive_In) C117.D15F(Coil_Out_to_Sat)
ISC_HAM1_228: C111.D25M(Air_Side) C112.D25F(Chan_1-4)
ISC_HAM1_229: C112.D25F(Chan_5-8) C116.D25M(Air_Side)

Not connected (* = marked no-connect by the designer): C107 Conec 3(DC_±18v)* D25F(PD_in_From_Sat)*; C112 Conec-3(DC_IN_+/-18)*; C117 Conec 3(DC_±18v)* D25F(PD_in_From_Sat)*

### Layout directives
Length: 45ft; DCC: D2100464: ISC_HAM1_228, ISC_HAM1_229
Length: 5ft; DCC: D2100753: ISC_HAM1_184, ISC_HAM1_185, ISC_HAM1_192, ISC_HAM1_193
Length: 48in; DCC: Connector J5(D): HAM1_289D, HAM1_291D
Length: 48in; DCC: Connector J4(C): HAM1_289C, HAM1_291C
Length: 48in; DCC: Connector J3(B): HAM1_289B, HAM1_291B
Length: 48in; DCC: Connector J2(A): HAM1_289A, HAM1_291A
Length: 80ft; DCC: D2200034: ISC_HAM1_194, ISC_HAM1_195
Length: 48in; DCC: Connector J1(E): HAM1_289E, HAM1_291E
Length: 9ft; DCC: D1000225: HAM1-290
Length: 15ft; DCC: D1000225: HAM1-292
Length: 80ft; DCC: D2200103: ISC_HAM1_125, ISC_HAM1_126

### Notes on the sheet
- RM1
- (near C111) L1 HAM1-D4-F4
- RM2
- (near C116) L1 HAM1-D4-F5

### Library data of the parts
C107 C117 = CD HAM-A D1100687: System: SUS; Serial: Sxxxxxxx
C108 C113 = 4-BOSEM Array UL-Type: Rack: R?; Slot: U?; Serial: Sxxxxxxx; System: SUS
C109 C114 = D1000228 D25 Quadrapus: Slot: U?; Rack: R?; Serial: Sxxxxxxx; System: SUS
C110 C115 = D1001346-2 1st Cable Bracket: as C28 on sheet MC1 and MC3 Top Masses
C111 = VacFeedD25: Serial: Sxxxxxxx; System: ISC; Rack: HAM1; Slot: D4-F4
C112 = Satellite Amplifier US D1002818: Serial: Sxxxxxxx
C116 = VacFeedD25: Serial: Sxxxxxxx; System: ISC; Rack: HAM1; Slot: D4-F5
